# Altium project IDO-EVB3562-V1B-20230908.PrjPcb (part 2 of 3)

## Sheet P15.SchDoc
size 420 x 297 mm
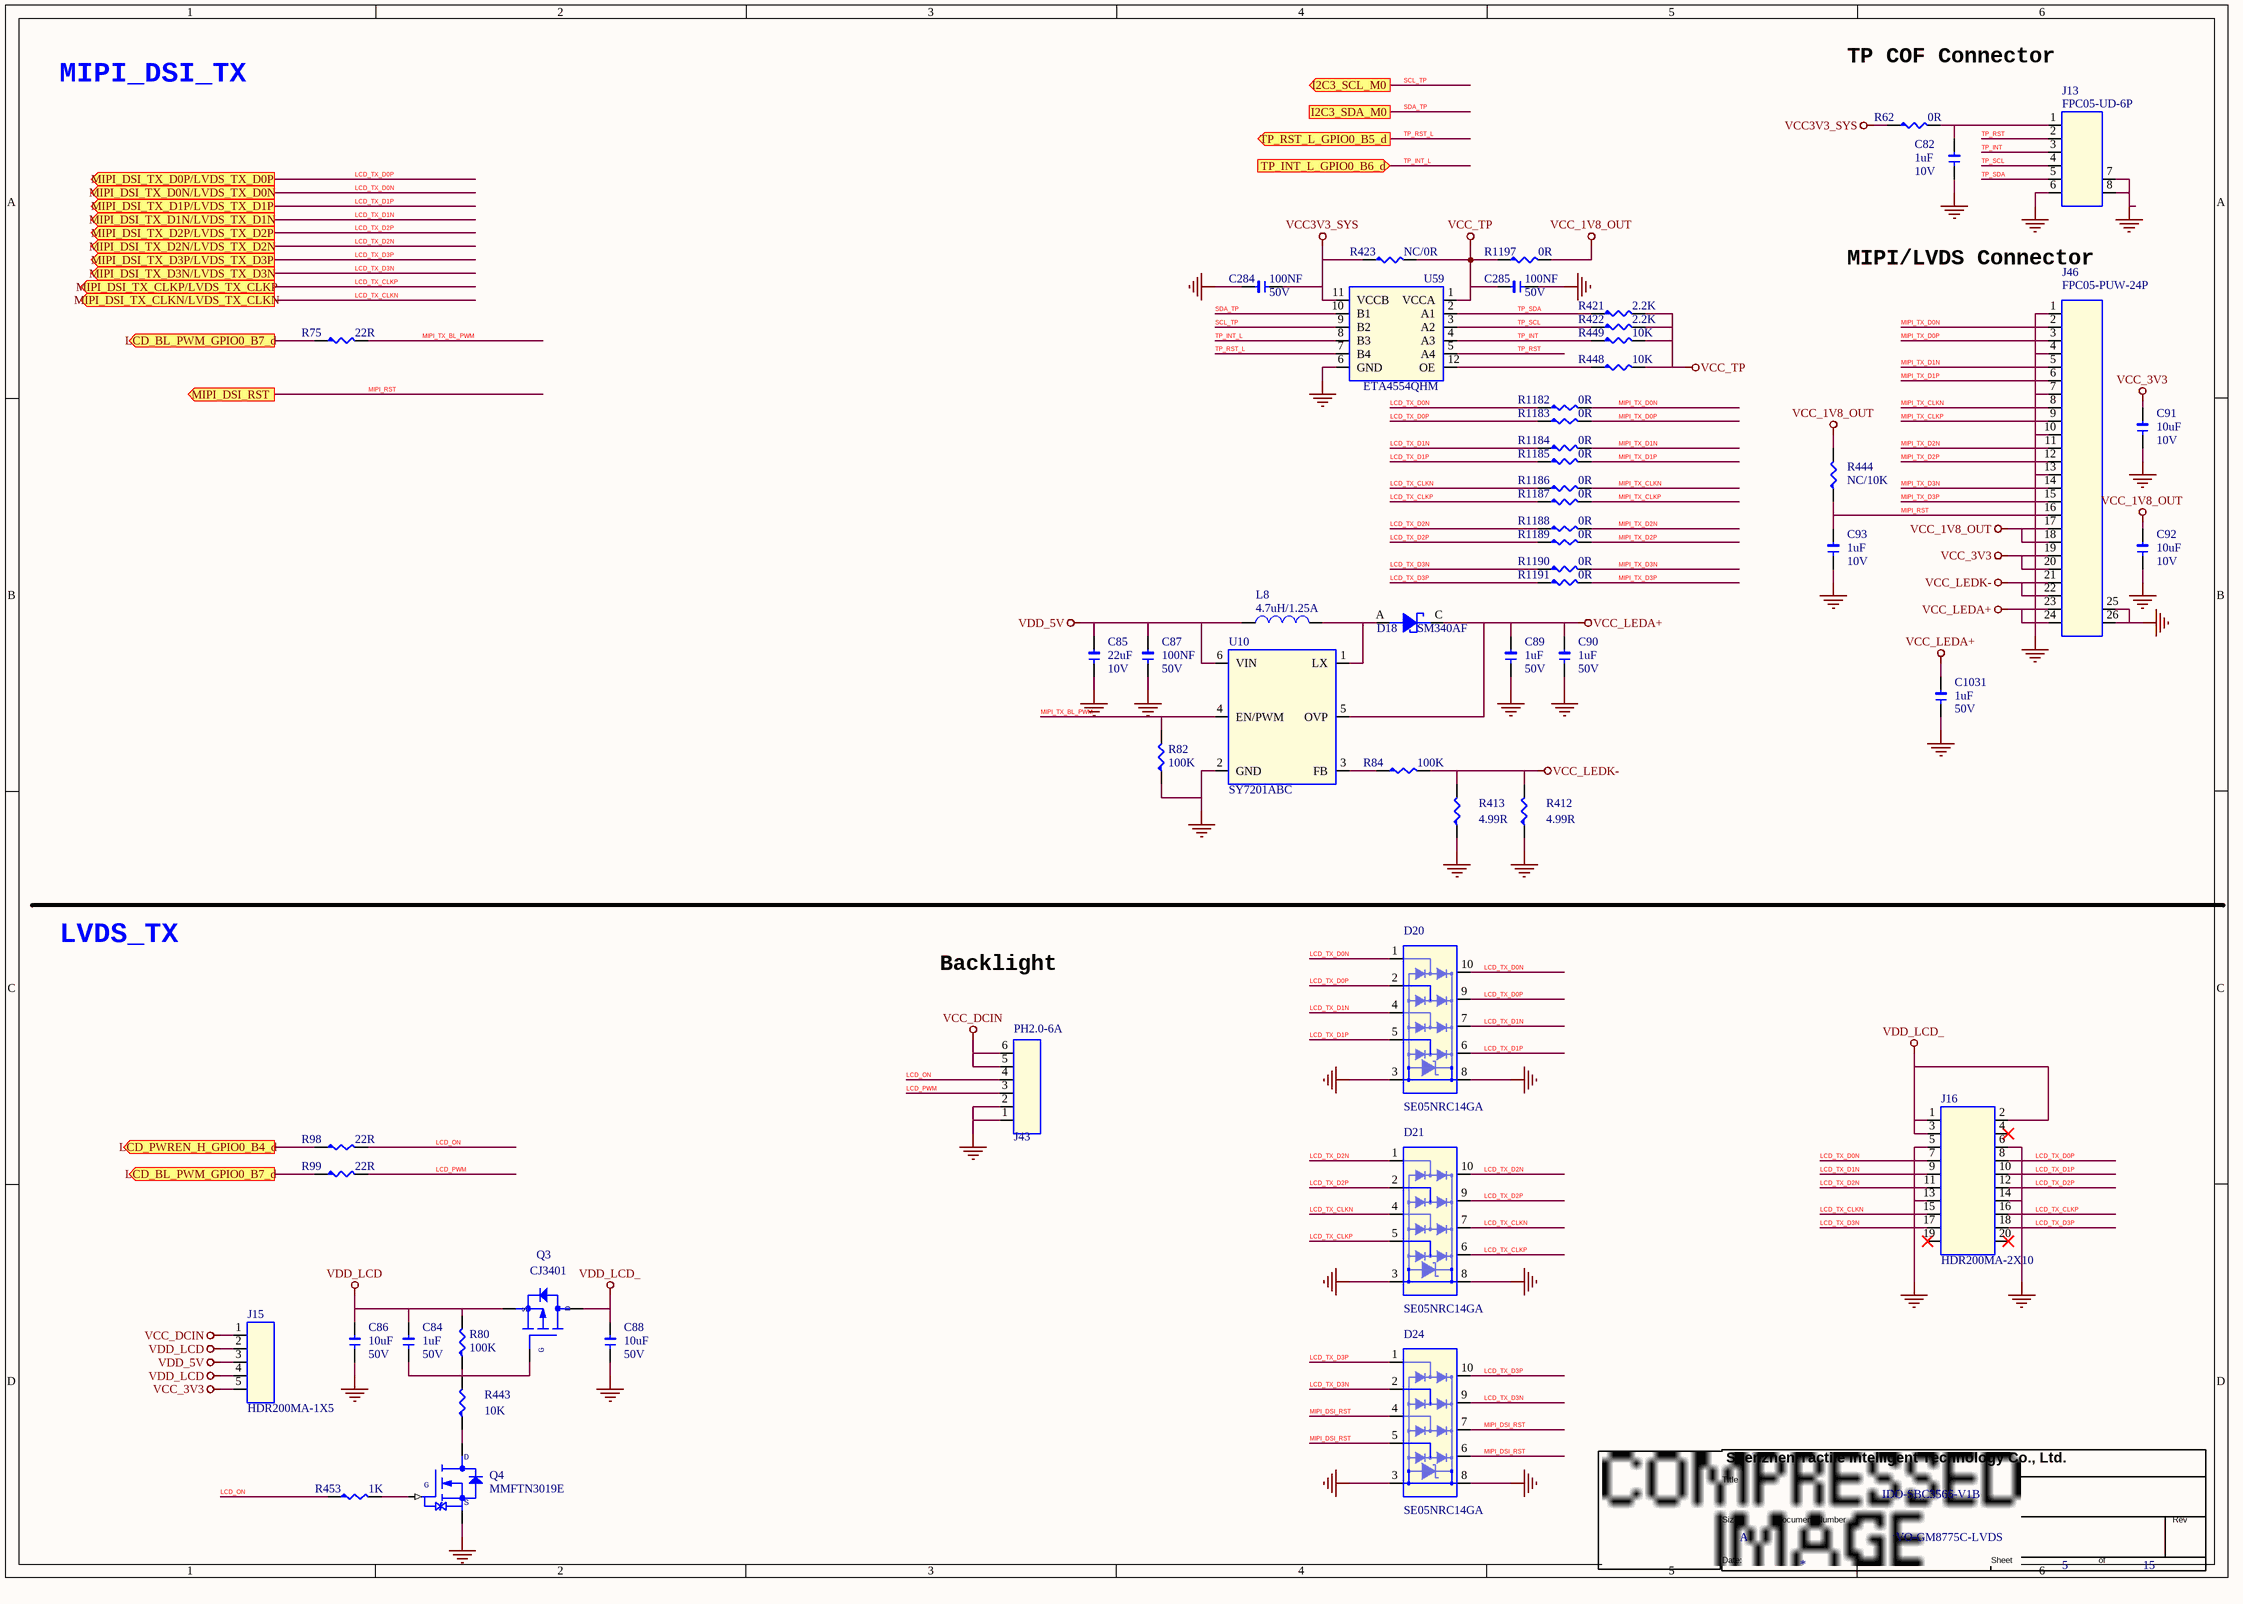
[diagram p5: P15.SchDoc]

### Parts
(Parts that share a designator on the sheet are numbered #1, #2 ... from top to bottom, then left to right.)
*#3  Page Count: 15  Page Number: 5  Page Size: A  Title: IDO-SBC3566-V1B  Doc: VO-GM8775C-LVDS  (hidden comment: TitleBlock1)  (graphical)
C82  1uF  DSC2: 10V  [1206]
C84  1uF  DSC2: 50V  [1206]
C85  22uF  DSC2: 10V  [1206]
C86  10uF  DSC2: 50V  [1206]
C87  100NF  DSC2: 50V  [1206]
C88  10uF  DSC2: 50V  [1206]
C89  1uF  DSC2: 50V  [1206]
C90  1uF  DSC2: 50V  [1206]
C91  10uF  DSC2: 10V  [1206]
C92  10uF  DSC2: 10V  [1206]
C93  1uF  DSC2: 10V  [1206]
C284  100NF  DSC2: 50V  [1206]
C285  100NF  DSC2: 50V  [1206]
C1031  1uF  DSC2: 50V  [1206]
D18  SM340AF  [SMAF]
D20  SE05NRC14GA  [DFN2510-10L]
D21  SE05NRC14GA  [DFN2510-10L]
D24  SE05NRC14GA  [DFN2510-10L]
J13  FPC05-UD-6P  [FPC05-6P]
J15  HDR200MA-1X5  [HDR200MA-1X5]
J16  HDR200MA-2X10  [HDR200MA-2X10]
J43  PH2.0-6A  [PH200-6A]
J46  FPC05-PUW-24P  [FPC05-24P]
L8  4.7uH/1.25A  [IND_252012]
Q3  CJ3401  [SOT23]
Q4  MMFTN3019E  [SOT523]
R62  0R  [R0402]
R75  22R  [R0402]
R80  100K  [R0402]
R82  100K  [R0402]
R84  100K  [R0402]
R98  22R  [R0402]
R99  22R  [R0402]
R412  4.99R  [R0603]
R413  4.99R  [R0603]
R421  2.2K  [R0402]
R422  2.2K  [R0402]
R423  NC/0R  [R0402]
R443  10K  [R0402]
R444  NC/10K  [R0402]
R448  10K  [R0402]
R449  10K  [R0402]
R453  1K  [R0402]
R1182  0R  [R0402]
R1183  0R  [R0402]
R1184  0R  [R0402]
R1185  0R  [R0402]
R1186  0R  [R0402]
R1187  0R  [R0402]
R1188  0R  [R0402]
R1189  0R  [R0402]
R1190  0R  [R0402]
R1191  0R  [R0402]
R1197  0R  [R0402]
U10  SY7201ABC  [SOT23-6]
U59  ETA4554QHM  [ETA4554-QFN12]

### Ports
I2C3_SCL_M0 (out), I2C3_SDA_M0, LCD_BL_PWM_GPIO0_B7_d (out), LCD_PWREN_H_GPIO0_B4_d (out), MIPI_DSI_RST (out), MIPI_DSI_TX_CLKN/LVDS_TX_CLKN (out), MIPI_DSI_TX_CLKP/LVDS_TX_CLKP (out), MIPI_DSI_TX_D0N/LVDS_TX_D0N (out), MIPI_DSI_TX_D0P/LVDS_TX_D0P (out), MIPI_DSI_TX_D1N/LVDS_TX_D1N (out), MIPI_DSI_TX_D1P/LVDS_TX_D1P (out), MIPI_DSI_TX_D2N/LVDS_TX_D2N (out), MIPI_DSI_TX_D2P/LVDS_TX_D2P (out), MIPI_DSI_TX_D3N/LVDS_TX_D3N (out), MIPI_DSI_TX_D3P/LVDS_TX_D3P (out), TP_INT_L_GPIO0_B6_d (in), TP_RST_L_GPIO0_B5_d (out)

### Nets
GND: C82.1 C85.1 C86.1 C87.1 C88.1 C89.1 C90.1 C91.1 C92.1 C93.1 C284.2 C285.1 C1031.1 D20.3 D20.8 D21.3 D21.8 D24.3 D24.8 J13.6 J13.7 J13.8 J16.5 J16.6 J16.13 J16.14 J43.1 J43.2 J46.1 J46.4 J46.7 J46.10 J46.13 J46.25 J46.26 Q4.2(SOURCE) R82.1 R412.1 R413.1 U10.2(GND) U59.6(GND)
VCC3V3_SYS: C284.1 R62.1 R423.1 U59.11(VCCB)
VCC_1V8_OUT: C92.2 J46.17 J46.18 R444.2 R1197.2
VCC_3V3: C91.2 J15.5 J46.19 J46.20
VCC_DCIN: J15.1 J43.5 J43.6
VCC_LEDA+: C89.2 C90.2 C1031.2 D18.C J46.23 J46.24 U10.5(OVP)
VCC_LEDK-: J46.21 J46.22 R84.2 R412.2 R413.2
VCC_TP: C285.2 R421.2 R422.2 R423.2 R448.2 R449.2 R1197.1 U59.1(VCCA)
VDD_5V: C85.2 C87.2 J15.3 L8.1 U10.6(VIN)
VDD_LCD: C84.2 C86.2 J15.2 J15.4 Q3.2(SOURCE) R80.2
VDD_LCD_: C88.2 J16.1 J16.2 J16.3 Q3.3(DRAIN)
LCD_ON: J43.4 R98.2 R453.1
LCD_PWM: J43.3 R99.2
LCD_TX_CLKN: D21.4 D21.7 J16.15 R1186.1 ; port MIPI_DSI_TX_CLKN/LVDS_TX_CLKN
LCD_TX_CLKP: D21.5 D21.6 J16.16 R1187.1 ; port MIPI_DSI_TX_CLKP/LVDS_TX_CLKP
LCD_TX_D0N: D20.1 D20.10 J16.7 R1182.1 ; port MIPI_DSI_TX_D0N/LVDS_TX_D0N
LCD_TX_D0P: D20.2 D20.9 J16.8 R1183.1 ; port MIPI_DSI_TX_D0P/LVDS_TX_D0P
LCD_TX_D1N: D20.4 D20.7 J16.9 R1184.1 ; port MIPI_DSI_TX_D1N/LVDS_TX_D1N
LCD_TX_D1P: D20.5 D20.6 J16.10 R1185.1 ; port MIPI_DSI_TX_D1P/LVDS_TX_D1P
LCD_TX_D2N: D21.1 D21.10 J16.11 R1188.1 ; port MIPI_DSI_TX_D2N/LVDS_TX_D2N
LCD_TX_D2P: D21.2 D21.9 J16.12 R1189.1 ; port MIPI_DSI_TX_D2P/LVDS_TX_D2P
LCD_TX_D3N: D24.2 D24.9 J16.17 R1190.1 ; port MIPI_DSI_TX_D3N/LVDS_TX_D3N
LCD_TX_D3P: D24.1 D24.10 J16.18 R1191.1 ; port MIPI_DSI_TX_D3P/LVDS_TX_D3P
MIPI_DSI_RST: D24.4 D24.5 D24.6 D24.7
MIPI_RST: C93.2 J46.16 R444.1 ; port MIPI_DSI_RST
MIPI_TX_BL_PWM: R75.2 R82.2 U10.4(EN/PWM)
MIPI_TX_CLKN: J46.8 R1186.2
MIPI_TX_CLKP: J46.9 R1187.2
MIPI_TX_D0N: J46.2 R1182.2
MIPI_TX_D0P: J46.3 R1183.2
MIPI_TX_D1N: J46.5 R1184.2
MIPI_TX_D1P: J46.6 R1185.2
MIPI_TX_D2N: J46.11 R1188.2
MIPI_TX_D2P: J46.12 R1189.2
MIPI_TX_D3N: J46.14 R1190.2
MIPI_TX_D3P: J46.15 R1191.2
SCL_TP: U59.9(B2) ; port I2C3_SCL_M0
SDA_TP: U59.10(B1) ; port I2C3_SDA_M0
TP_INT: J13.3 R449.1 U59.4(A3)
TP_INT_L: U59.8(B3) ; port TP_INT_L_GPIO0_B6_d
TP_RST: J13.2 U59.5(A4)
TP_RST_L: U59.7(B4) ; port TP_RST_L_GPIO0_B5_d
TP_SCL: J13.4 R422.1 U59.3(A2)
TP_SDA: J13.5 R421.1 U59.2(A1)
NetC82_2: C82.2 J13.1 R62.2
NetC84_1: C84.1 Q3.1(GATE) R80.1 R443.2
NetD18_A: D18.A L8.2 U10.1(LX)
NetM1_154: R98.1 ; port LCD_PWREN_H_GPIO0_B4_d
NetM1_157: R75.1 R99.1 ; port LCD_BL_PWM_GPIO0_B7_d
NetQ4_1: Q4.1(GATE) R453.2
NetQ4_3: Q4.3(DRAIN) R443.1
NetR84_1: R84.1 U10.3(FB)
NetR448_1: R448.1 U59.12(OE)

Not connected (* = marked no-connect by the designer): J16 4* 19* 20*

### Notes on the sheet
- MIPI_DSI_TX
- TP COF Connector
- MIPI/LVDS Connector
- LVDS_TX
- Backlight

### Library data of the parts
C82 = C-0402_Dup1: Part Number: C020102120064; Part Name: 贴片电容; Manufacture: 三星¦国巨¦村田; PCB Footprint: C0402; ERP Number: 1010200054; DSC1: ±10%; DSC3: X5R; ID: 64
C84 C89 C90 C1031 = C-0603: Manufacture: 三星¦国巨¦村田; Part Name: 贴片电容; Part Number: C020102120069; PCB Footprint: C0603; ID: 69; DSC3: X5R; DSC1: ±10%; ERP Number: 1010200142
C85 = C-0603: Manufacture: 三星¦国巨¦村田; Part Name: 贴片电容; Part Number: C020107143899; PCB Footprint: C0603; ID: 83; DSC3: X5R; DSC1: ±20%
C86 = C-1206_Dup1: Part Number: C020103263826; Part Name: 贴片电容; Manufacture: 三星¦国巨¦村田; DSC1: ±10%; DSC3: X5R; ID: 79; PCB Footprint: C1206
C87 = C-0402_Dup1: Manufacture: 三星¦国巨¦村田; Part Name: 贴片电容; Part Number: C020102120061; PCB Footprint: C0402; ID: 61; DSC3: X7R; DSC1: ±10%; ERP Number: 1010200128
C88 = C-1206_Dup1: Manufacture: 三星¦国巨¦村田; Part Name: 贴片电容; Part Number: C020103263826; ID: 79; DSC3: X5R; DSC1: ±10%; PCB Footprint: C1206
C91 C92 = C-0603: Part Number: C020102120071; Part Name: 贴片电容; Manufacture: 三星¦国巨¦村田; PCB Footprint: C0603; ERP Number: 1010200076; DSC1: ±20%; DSC3: X5R; ID: 71
C93 = C-0402_Dup1: Manufacture: 三星¦国巨¦村田; Part Name: 贴片电容; Part Number: C020102120064; PCB Footprint: C0402; ID: 64; DSC3: X5R; DSC1: ±10%; ERP Number: 1010200054
C284 C285 = C-0402_Dup1: Manufacture: 三星¦国巨¦村田; Part Name: 贴片电容; Part Number: C020102120061; ID: 61; DSC3: X7R; DSC1: ±10%; ERP Number: 1010200128; PCB Footprint: C0402
D18 = DI-XI-S: Manufacture: 乐山无线电; Part Name: 肖特基二级管; Part Number: C040202220007; CLASS: IC; Solder: 推荐; ID: 7; DSC3: VF=500mV/3A; DSC2: IF=3A; DSC1: VR=40V
D20 D21 = DI-ESD-SE05NRC14GA: Manufacture: 硕凯; Part Number: C040504013981; Part Name: ESD; Solder: 推荐; ID: 8; DSC5: Cj=0.4pF; DSC4: Vc=20V; DSC3: Vbr=8V; DSC2: Vdc=5V; DSC1: 双向
D24 = DI-ESD-SE05NRC14GA: Part Name: ESD; Part Number: C040504013981; Manufacture: 硕凯; DSC1: 双向; DSC2: Vdc=5V; DSC3: Vbr=8V; DSC4: Vc=20V; DSC5: Cj=0.4pF; ID: 8; Solder: 推荐
J13 = J-FPC-6P: Part Name: FPC座; DSC1: 6P; DSC2: 0.5mm间距; DSC3: 双面触点 前插后压 卧贴; DSC4: H=2mm; DSC5: 镀锡; DSC6: X05A20H06T（星坤）; ID: 41
J15 = J-HDR-5: Part Number: J010203194650; Part Name: 单排针; DSC1: 单排单塑; DSC2: 1x5; DSC3: 2mm脚距; DSC4: 通孔直针; DSC5: 针长8.8mm  2.8+2(H塑高)+4 mm; DSC6: 黑胶; DSC7: X4611WV-05I-C28D40（星坤）; ID: 82
J16 = J-HDR-D-20: Part Number: J010102760009; Part Name: 双排针; DSC1: 双排单塑; DSC2: 2x10; DSC3: 2mm脚距; DSC4: 通孔直针; DSC5: 针长8.8mm  2.8+2(H塑高)+4 mm; DSC6: 黑胶; DSC7: X4621WV-2x10I-C28D40（星坤）; ID: 9
J43 = J-H-6P: Part Name: PH; DSC1: 6p; DSC2: 2.0mm间距; DSC3: 通孔180度直针; DSC4: 红色胶壳 耐高温; DSC5: A2001WV-6P-1-RD(CJT); ID: 80
J46 = J-FPC-24P: Part Name: FPC座; Part Number: J030102870021; ID: 34; DSC6: X05B20U24T(星坤); DSC5: 镀锡; DSC4: H=2mm; DSC3: 上接 抽拉式 卧贴; DSC2: 0.5mm间距; DSC1: 24P
L8 = L-IND_Dup1: Manufacture: 宗成¦长江微电¦顺络; Part Name: 功率电感; ID: 54; DSC8: ZCRH252012-4.7uH-M(宗成); DSC7: FHD252012S-4R7MT(长江微电); DSC6: WPN252012H4R7MT(顺络); DSC5: 2.5*2.0*1.2mm; DSC4: 260mΩ; DSC3: Irms=1.25A; DSC2: Isat=1.6A; DSC1: ±20%
Q3 = P-MOS: Part Number: C030202190001; Manufacture: 长电; ERP Number: 1010800001; DSC1: Vds=-30V; DSC2: Id=-4.2A; DSC3: Vgs(th)=-1.3V; DSC4: Vgs=±12V; DSC5: pd=350mW; ID: 1
Q4 = N-MOS-Q: Part Number: C030202190004; Part Name: N-MOS; Manufacture: 先科; ERP Number: 1010800011; DSC1: Vds=30V; DSC2: Id=100mA; DSC3: Vgs(th)=1.5V; DSC4: Vgs=±20V; DSC5: pd=150mW; ID: 4
R62 R1197 = R-0402_Dup3: Part Name: 贴片电阻; Part Number: C011002080413; DSC1: ±1%; DSC2: 1/16W; ID: 413
R75 R98 R99 = R-0402_Dup3: Part Name: 贴片电阻; Part Number: C011002080262; ERP Number: 1010200173; DSC1: ±5%; DSC2: 1/16W; ID: 262
R80 R82 R84 = R-0402_Dup3: Part Number: C011002080353; Part Name: 贴片电阻; ID: 353; DSC2: 1/16W; DSC1: ±5%; ERP Number: 1010200103
R412 = R-0603_Dup1: Part Number: C011002081238; Part Name: 贴片电阻; ID: 1,238; DSC2: 1/10W; DSC1: ±1%
R413 = R-0603_Dup1: Part Name: 贴片电阻; Part Number: C011002081238; DSC1: ±1%; DSC2: 1/10W; ID: 1,238
R421 R422 = R-0402_Dup3: Part Number: C011002080778; Part Name: 贴片电阻; ID: 778; DSC2: 1/16W; DSC1: ±1%
R423 = R-0402_Dup3: Part Number: C011002080413; Part Name: 贴片电阻; ID: 413; DSC2: 1/16W; DSC1: ±1%
R443 R444 = R-0402_Dup3: Part Number: C011002080856; Part Name: 贴片电阻; ID: 856; DSC2: 1/16W; DSC1: ±1%; ERP Number: 1010200140
R448 R449 = R-0402_Dup3: Part Name: 贴片电阻; Part Number: C011002080856; ERP Number: 1010200140; DSC1: ±1%; DSC2: 1/16W; ID: 856
R453 = R-0402_Dup3: Part Name: 贴片电阻; Part Number: C011002080742; ERP Number: 1010200113; DSC1: ±1%; DSC2: 1/16W; ID: 742
R1182-R1191 = R-0402_Dup3: Part Name: 贴片电阻; Part Number: C011002080217; ERP Number: 1010200100; DSC1: ±5%; DSC2: 1/16W; ID: 217
U10 = U-SY7201ABC: Manufacture: 矽力杰; Part Number: C070202410024; Part Name: DCDC; ID: 24; Solder: 量产; DSC7: Boost LED驱动; DSC6: 1MHz; DSC5: 0.9; DSC4: Vfb=200mV; DSC3: Io=2A; DSC2: Vo=30V; DSC1: Vi=2.5-30V; ERP Number: 1010100053
U59 = U-ETA4554QHM: Part Name: 逻辑缓冲器; Part Number: C080105124705; Manufacture: ETA 钰泰; DSC1: 4位 高速缓冲 24Mbps VCC=1.65V-5.5V; DSC2: QFN12; DSC3: -40℃~+85℃; ID: 11

## Sheet P16.SchDoc
size 420 x 297 mm
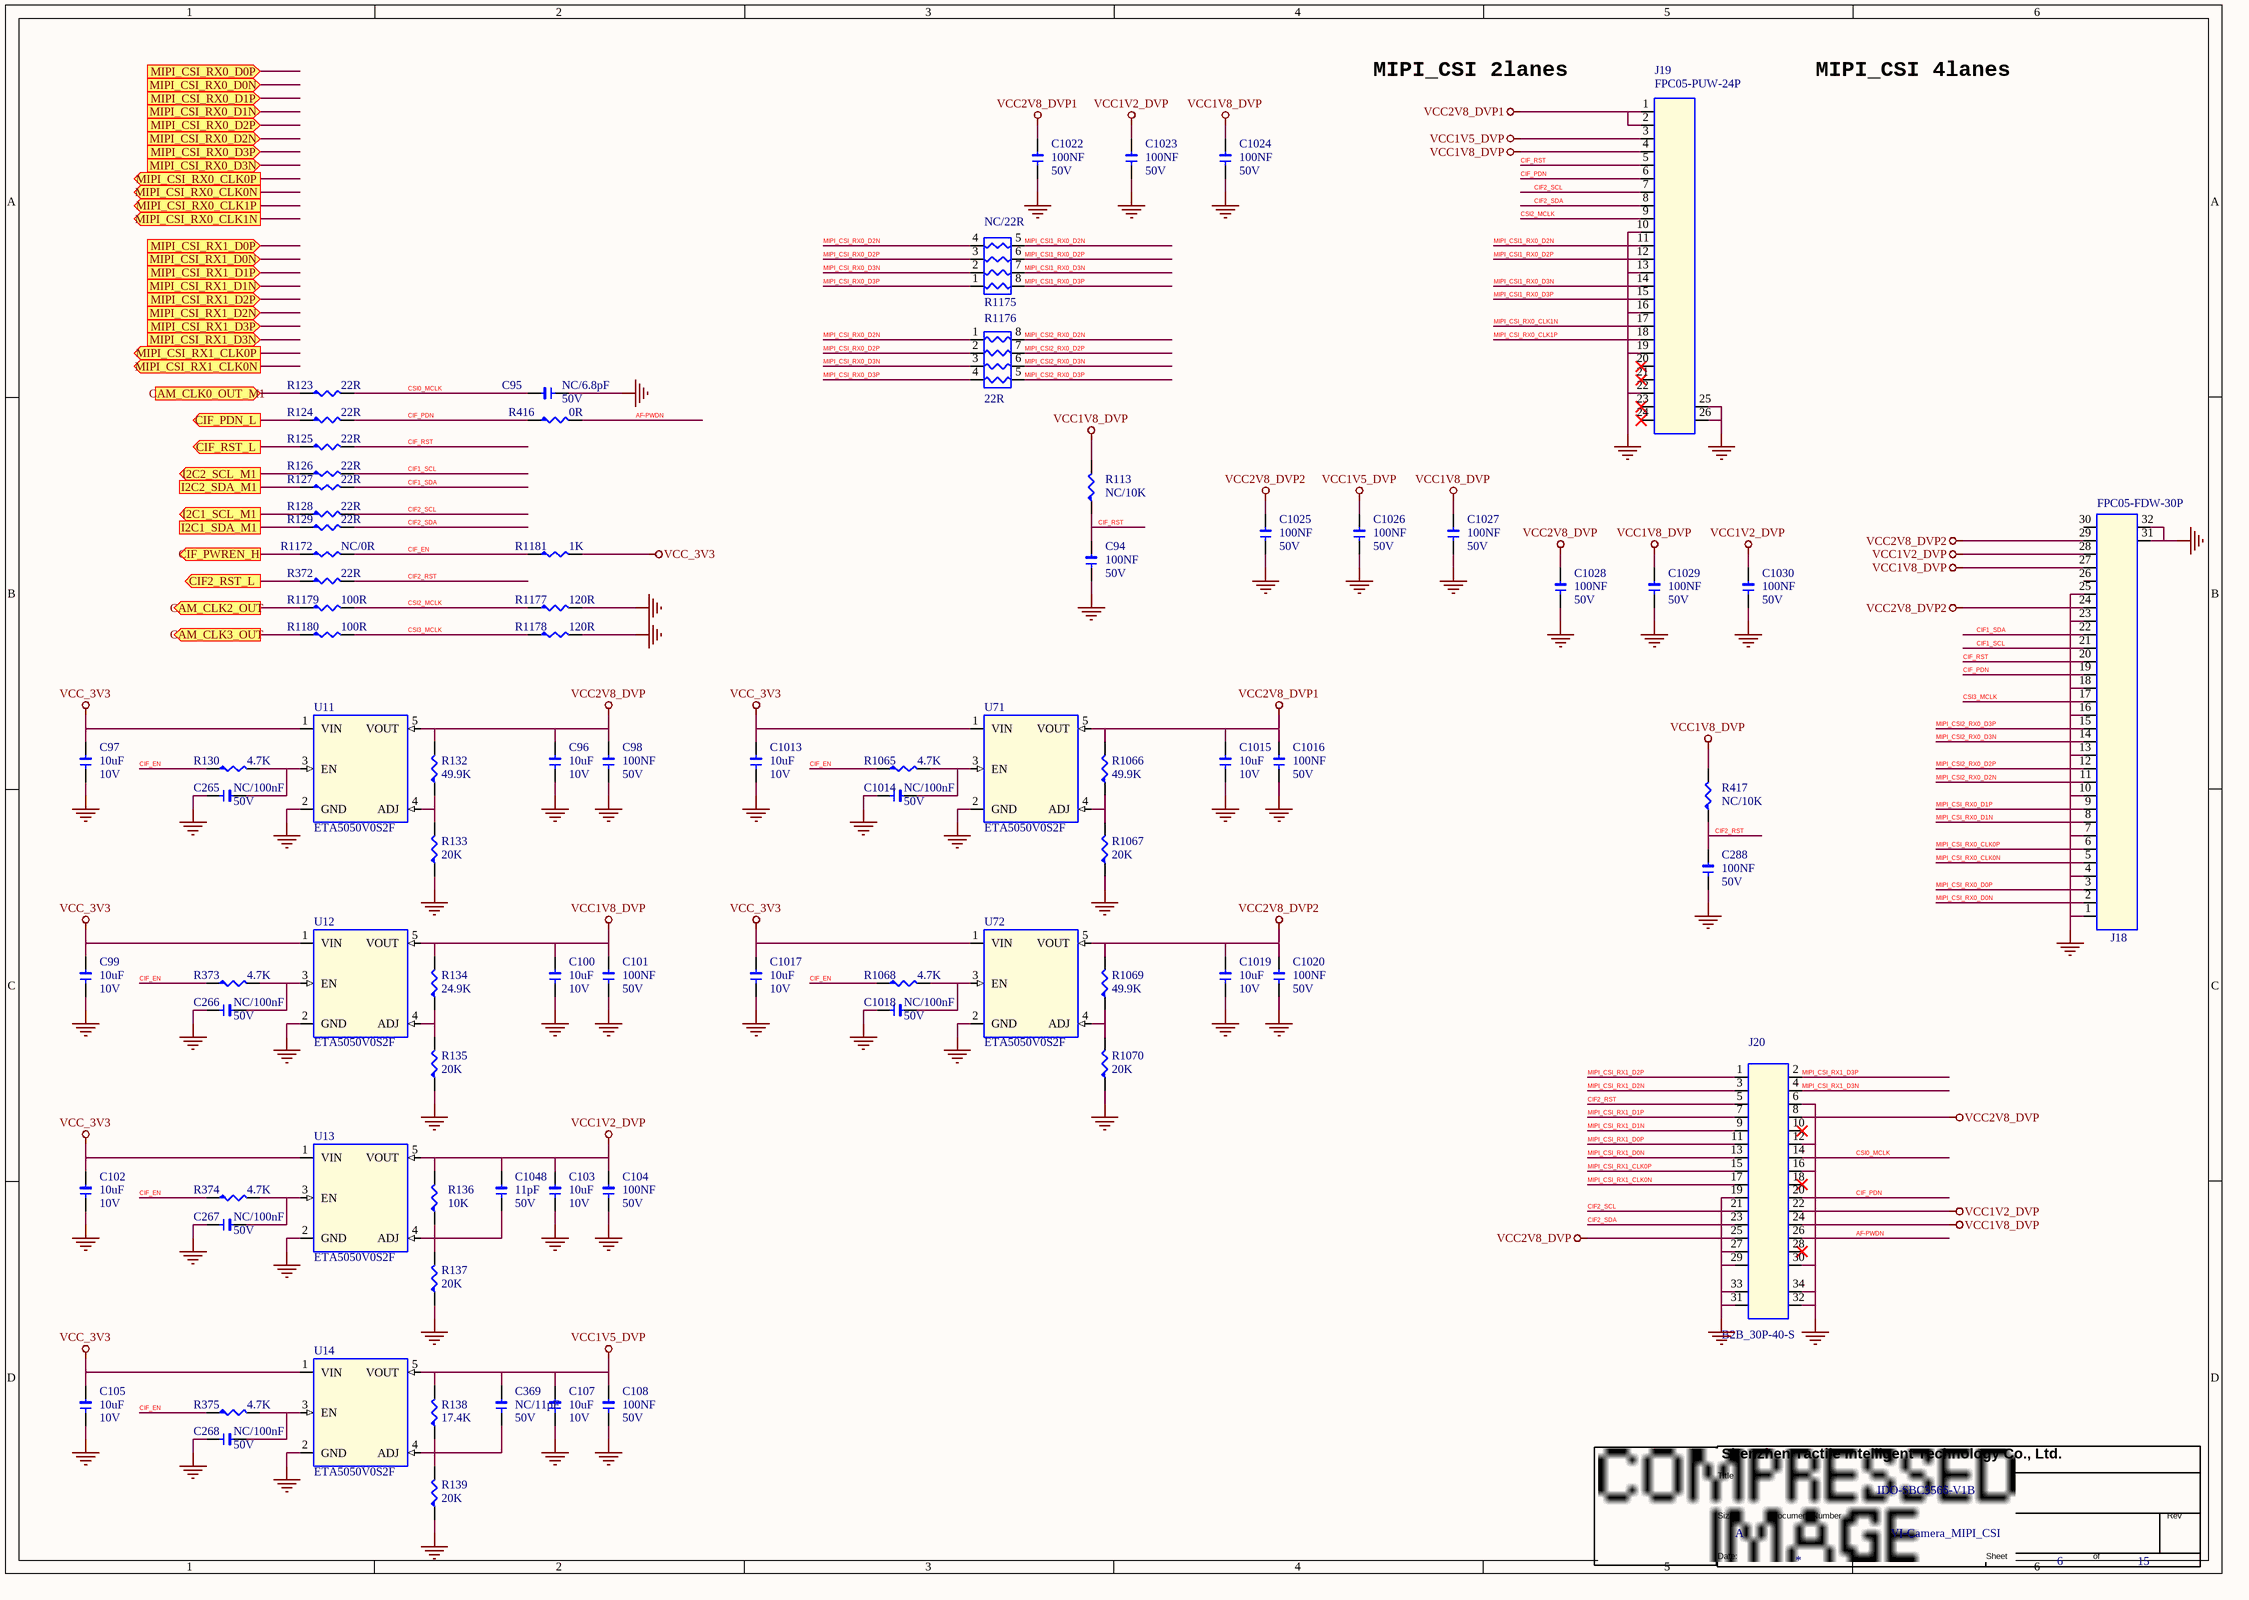
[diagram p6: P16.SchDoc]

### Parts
(Parts that share a designator on the sheet are numbered #1, #2 ... from top to bottom, then left to right.)
*#4  Page Count: 15  Page Number: 6  Page Size: A  Title: IDO-SBC3566-V1B  Doc: VI-Camera_MIPI_CSI  (hidden comment: TitleBlock1)  (graphical)
C94  100NF  DSC2: 50V  [1206]
C95  NC/6.8pF  DSC2: 50V  [1206]
C96  10uF  DSC2: 10V  [1206]
C97  10uF  DSC2: 10V  [1206]
C98  100NF  DSC2: 50V  [1206]
C99  10uF  DSC2: 10V  [1206]
C100  10uF  DSC2: 10V  [1206]
C101  100NF  DSC2: 50V  [1206]
C102  10uF  DSC2: 10V  [1206]
C103  10uF  DSC2: 10V  [1206]
C104  100NF  DSC2: 50V  [1206]
C105  10uF  DSC2: 10V  [1206]
C107  10uF  DSC2: 10V  [1206]
C108  100NF  DSC2: 50V  [1206]
C265  NC/100nF  DSC2: 50V  [1206]
C266  NC/100nF  DSC2: 50V  [1206]
C267  NC/100nF  DSC2: 50V  [1206]
C268  NC/100nF  DSC2: 50V  [1206]
C288  100NF  DSC2: 50V  [1206]
C369  NC/11pF  DSC2: 50V  [1206]
C1013  10uF  DSC2: 10V  [1206]
C1014  NC/100nF  DSC2: 50V  [1206]
C1015  10uF  DSC2: 10V  [1206]
C1016  100NF  DSC2: 50V  [1206]
C1017  10uF  DSC2: 10V  [1206]
C1018  NC/100nF  DSC2: 50V  [1206]
C1019  10uF  DSC2: 10V  [1206]
C1020  100NF  DSC2: 50V  [1206]
C1022  100NF  DSC2: 50V  [1206]
C1023  100NF  DSC2: 50V  [1206]
C1024  100NF  DSC2: 50V  [1206]
C1025  100NF  DSC2: 50V  [1206]
C1026  100NF  DSC2: 50V  [1206]
C1027  100NF  DSC2: 50V  [1206]
C1028  100NF  DSC2: 50V  [1206]
C1029  100NF  DSC2: 50V  [1206]
C1030  100NF  DSC2: 50V  [1206]
C1048  11pF  DSC2: 50V  [1206]
J18  FPC05-FDW-30P  [FPC05-30P]
J19  FPC05-PUW-24P  [FPC05-24P]
J20  B2B_30P-40-S  [B2B_30P-40-S]
R113  NC/10K  [R0402]
R123  22R  [R0402]
R124  22R  [R0402]
R125  22R  [R0402]
R126  22R  [R0402]
R127  22R  [R0402]
R128  22R  [R0402]
R129  22R  [R0402]
R130  4.7K  [R0402]
R132  49.9K  [R0402]
R133  20K  [R0402]
R134  24.9K  [R0402]
R135  20K  [R0402]
R136  10K  [R0402]
R137  20K  [R0402]
R138  17.4K  [R0402]
R139  20K  [R0402]
R372  22R  [R0402]
R373  4.7K  [R0402]
R374  4.7K  [R0402]
R375  4.7K  [R0402]
R416  0R  [R0402]
R417  NC/10K  [R0402]
R1065  4.7K  [R0402]
R1066  49.9K  [R0402]
R1067  20K  [R0402]
R1068  4.7K  [R0402]
R1069  49.9K  [R0402]
R1070  20K  [R0402]
R1172  NC/0R  [R0402]
R1175  NC/22R  [RN_0402X4]
R1176  22R  [RN_0402X4]
R1177  120R  [R0402]
R1178  120R  [R0402]
R1179  100R  [R0402]
R1180  100R  [R0402]
R1181  1K  [R0402]
U11  ETA5050V0S2F  [SOT23-5]
U12  ETA5050V0S2F  [SOT23-5]
U13  ETA5050V0S2F  [SOT23-5]
U14  ETA5050V0S2F  [SOT23-5]
U71  ETA5050V0S2F  [SOT23-5]
U72  ETA5050V0S2F  [SOT23-5]

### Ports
CAM_CLK0_OUT_M1 (in), CAM_CLK2_OUT (out), CAM_CLK3_OUT (out), CIF2_RST_L (out), CIF_PDN_L (out), CIF_PWREN_H (out), CIF_RST_L (out), I2C1_SCL_M1 (out), I2C1_SDA_M1, I2C2_SCL_M1 (out), I2C2_SDA_M1, MIPI_CSI_RX0_CLK0N (out), MIPI_CSI_RX0_CLK0P (out), MIPI_CSI_RX0_CLK1N (out), MIPI_CSI_RX0_CLK1P (out), MIPI_CSI_RX0_D0N (in), MIPI_CSI_RX0_D0P (in), MIPI_CSI_RX0_D1N (in), MIPI_CSI_RX0_D1P (in), MIPI_CSI_RX0_D2N (in), MIPI_CSI_RX0_D2P (in), MIPI_CSI_RX0_D3N (in), MIPI_CSI_RX0_D3P (in), MIPI_CSI_RX1_CLK0N (out), MIPI_CSI_RX1_CLK0P (out), MIPI_CSI_RX1_D0N (in), MIPI_CSI_RX1_D0P (in), MIPI_CSI_RX1_D1N (in), MIPI_CSI_RX1_D1P (in), MIPI_CSI_RX1_D2N (in), MIPI_CSI_RX1_D2P (in), MIPI_CSI_RX1_D3N (in), MIPI_CSI_RX1_D3P (in)

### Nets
GND: C94.1 C95.1 C96.1 C97.1 C98.1 C99.1 C100.1 C101.1 C102.1 C103.1 C104.1 C105.1 C107.1 C108.1 C265.1 C266.1 C267.1 C268.1 C288.1 C1013.1 C1014.1 C1015.1 C1016.1 C1017.1 C1018.1 C1019.1 C1020.1 C1022.1 C1023.1 C1024.1 C1025.1 C1026.1 C1027.1 C1028.1 C1029.1 C1030.1 J18.1 J18.4 J18.7 J18.10 J18.13 J18.16 J18.18 J18.23 J18.25 J18.31 J18.32 J19.10 J19.13 J19.16 J19.19 J19.22 J19.25 J19.26 J20.6 J20.12 J20.16 J20.19 J20.27 J20.29 J20.30 J20.31 J20.32 J20.33 J20.34 R133.1 R135.1 R137.1 R139.1 R1067.1 R1070.1 R1177.2 R1178.2 U11.2(GND) U12.2(GND) U13.2(GND) U14.2(GND) U71.2(GND) U72.2(GND)
VCC1V2_DVP: C103.2 C104.2 C1023.2 C1030.2 C1048.2 J18.28 J20.22 R136.2 U13.5(VOUT)
VCC1V5_DVP: C107.2 C108.2 C369.2 C1026.2 J19.3 R138.2 U14.5(VOUT)
VCC1V8_DVP: C100.2 C101.2 C1024.2 C1027.2 C1029.2 J18.27 J19.4 J20.24 R113.2 R134.2 R417.2 U12.5(VOUT)
VCC2V8_DVP: C96.2 C98.2 C1028.2 J20.8 J20.25 R132.2 U11.5(VOUT)
VCC2V8_DVP1: C1015.2 C1016.2 C1022.2 J19.1 J19.2 R1066.2 U71.5(VOUT)
VCC2V8_DVP2: C1019.2 C1020.2 C1025.2 J18.24 J18.29 R1069.2 U72.5(VOUT)
VCC_3V3: C97.2 C99.2 C102.2 C105.2 C1013.2 C1017.2 R1181.2 U11.1(VIN) U12.1(VIN) U13.1(VIN) U14.1(VIN) U71.1(VIN) U72.1(VIN)
AF-PWDN: J20.26 R416.2
CIF1_SCL: J18.21 R126.2
CIF1_SDA: J18.22 R127.2
CIF2_RST: C288.2 J20.5 R372.2 R417.1
CIF2_SCL: J19.7 J20.21 R128.2
CIF2_SDA: J19.8 J20.23 R129.2
CIF_EN: R130.1 R373.1 R374.1 R375.1 R1065.1 R1068.1 R1172.2 R1181.1
CIF_PDN: J18.19 J19.6 J20.20 R124.2 R416.1
CIF_RST: C94.2 J18.20 J19.5 R113.1 R125.2
CSI0_MCLK: C95.2 J20.14 R123.2
CSI2_MCLK: J19.9 R1177.1 R1179.2
CSI3_MCLK: J18.17 R1178.1 R1180.2
MIPI_CSI1_RX0_D2N: J19.11 R1175.5
MIPI_CSI1_RX0_D2P: J19.12 R1175.6
MIPI_CSI1_RX0_D3N: J19.14 R1175.7
MIPI_CSI1_RX0_D3P: J19.15 R1175.8
MIPI_CSI2_RX0_D2N: J18.11 R1176.8
MIPI_CSI2_RX0_D2P: J18.12 R1176.7
MIPI_CSI2_RX0_D3N: J18.14 R1176.6
MIPI_CSI2_RX0_D3P: J18.15 R1176.5
MIPI_CSI_RX0_CLK0N: J18.5
MIPI_CSI_RX0_CLK0P: J18.6
MIPI_CSI_RX0_CLK1N: J19.17
MIPI_CSI_RX0_CLK1P: J19.18
MIPI_CSI_RX0_D0N: J18.2
MIPI_CSI_RX0_D0P: J18.3
MIPI_CSI_RX0_D1N: J18.8
MIPI_CSI_RX0_D1P: J18.9
MIPI_CSI_RX0_D2N: R1175.4 R1176.1
MIPI_CSI_RX0_D2P: R1175.3 R1176.2
MIPI_CSI_RX0_D3N: R1175.2 R1176.3
MIPI_CSI_RX0_D3P: R1175.1 R1176.4
MIPI_CSI_RX1_CLK0N: J20.17
MIPI_CSI_RX1_CLK0P: J20.15
MIPI_CSI_RX1_D0N: J20.13
MIPI_CSI_RX1_D0P: J20.11
MIPI_CSI_RX1_D1N: J20.9
MIPI_CSI_RX1_D1P: J20.7
MIPI_CSI_RX1_D2N: J20.3
MIPI_CSI_RX1_D2P: J20.1
MIPI_CSI_RX1_D3N: J20.4
MIPI_CSI_RX1_D3P: J20.2
NetC265_2: C265.2 R130.2 U11.3(EN)
NetC266_2: C266.2 R373.2 U12.3(EN)
NetC267_2: C267.2 R374.2 U13.3(EN)
NetC268_2: C268.2 R375.2 U14.3(EN)
NetC369_1: C369.1 R138.1 R139.2 U14.4(ADJ)
NetC1014_2: C1014.2 R1065.2 U71.3(EN)
NetC1018_2: C1018.2 R1068.2 U72.3(EN)
NetC1048_1: C1048.1 R136.1 R137.2 U13.4(ADJ)
NetM1_83: R1180.1 ; port CAM_CLK3_OUT
NetM1_84: R1179.1 ; port CAM_CLK2_OUT
NetM1_87: R1172.1 ; port CIF_PWREN_H
NetM1_88: R372.1 ; port CIF2_RST_L
NetM1_89: R124.1 ; port CIF_PDN_L
NetM1_90: R125.1 ; port CIF_RST_L
NetM1_93: R126.1 ; port I2C2_SCL_M1
NetM1_94: R127.1 ; port I2C2_SDA_M1
NetM1_109: R123.1 ; port CAM_CLK0_OUT_M1
NetM1_112: R128.1 ; port I2C1_SCL_M1
NetM1_113: R129.1 ; port I2C1_SDA_M1
NetR132_1: R132.1 R133.2 U11.4(ADJ)
NetR134_1: R134.1 R135.2 U12.4(ADJ)
NetR1066_1: R1066.1 R1067.2 U71.4(ADJ)
NetR1069_1: R1069.1 R1070.2 U72.4(ADJ)

Not connected (* = marked no-connect by the designer): J18 26 30; J19 20* 21* 23* 24*; J20 10* 18* 28*

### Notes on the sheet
- MIPI_CSI 2lanes
- MIPI_CSI 4lanes

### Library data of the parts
C94 = C-0402_Dup1: Part Number: C020102120061; Part Name: 贴片电容; Manufacture: 三星¦国巨¦村田; PCB Footprint: C0402; ERP Number: 1010200128; DSC1: ±10%; DSC3: X7R; ID: 61
C95 = C-0402_Dup1: Part Number: C020102120018; Part Name: 贴片电容; Manufacture: 三星¦国巨¦村田; PCB Footprint: C0402; ERP Number: 1010200056; DSC1: ±0.25PF; DSC3: C0G; ID: 18
C96 C100 C103 C107 = C-0603: Manufacture: 三星¦国巨¦村田; Part Name: 贴片电容; Part Number: C020102120071; PCB Footprint: C0603; ID: 71; DSC3: X5R; DSC1: ±20%; ERP Number: 1010200076
C97 C99 C102 C105 = C-0603: as C91 on sheet P15
C98 C101 C104 C108 C265-C268 C1022 C1024 C1026 C1028 C1030 = C-0402_Dup2: Manufacture: 三星¦国巨¦村田; Part Name: 贴片电容; Part Number: C020102120061; PCB Footprint: C0402; ID: 61; DSC3: X7R; DSC1: ±10%; ERP Number: 1010200128
C288 = C-0402_Dup1: as C87 on sheet P15
C369 = C-0402_Dup1: Part Number: C020102120022; Part Name: 贴片电容; Manufacture: 三星¦国巨¦村田; DSC1: ±5%; DSC3: C0G; ID: 22; PCB Footprint: C0402
C1013 C1017 = C-0603: Part Number: C020102120071; Part Name: 贴片电容; Manufacture: 三星¦国巨¦村田; ERP Number: 1010200076; DSC1: ±20%; DSC3: X5R; ID: 71; PCB Footprint: C0603
C1014 C1016 C1018 C1020 = C-0402_Dup2: Manufacture: 三星¦国巨¦村田; Part Name: 贴片电容; Part Number: C020102120061; ID: 61; DSC3: X7R; DSC1: ±10%; ERP Number: 1010200128; PCB Footprint: C0402
C1015 C1019 = C-0603: Manufacture: 三星¦国巨¦村田; Part Name: 贴片电容; Part Number: C020102120071; ID: 71; DSC3: X5R; DSC1: ±20%; ERP Number: 1010200076; PCB Footprint: C0603
C1023 C1025 C1027 C1029 = C-0402_Dup2: Part Number: C020102120061; Part Name: 贴片电容; Manufacture: 三星¦国巨¦村田; PCB Footprint: C0402; ERP Number: 1010200128; DSC1: ±10%; DSC3: X7R; ID: 61
C1048 = C-0402_Dup1: Manufacture: 三星¦国巨¦村田; Part Name: 贴片电容; Part Number: C020102120022; ID: 22; DSC3: C0G; DSC1: ±5%; PCB Footprint: C0402
J18 = J-FPC-30P: Part Name: FPC座; Part Number: J030102870078; ID: 19; DSC6: X05A20L30T(星坤); DSC5: 镀锡; DSC4: H=2mm; DSC3: 下接 翻盖 卧贴; DSC2: 0.5mm间距; DSC1: 30P
J19 = J-FPC-24P: as J46 on sheet P15
J20 = J-FPC-30P_1: Part Name: BTB座; ID: 19; DSC1: 30P
R113 R136 = R-0402_Dup3: as R448 on sheet P15
R123 = R-0402_Dup3: as R75 on sheet P15
R124-R129 R372 = R-0402_Dup3: Part Number: C011002080262; Part Name: 贴片电阻; ID: 262; DSC2: 1/16W; DSC1: ±5%; ERP Number: 1010200173
R130 R373-R375 R1065 R1068 = R-0402_Dup3: Part Number: C011002080818; Part Name: 贴片电阻; ID: 818; DSC2: 1/16W; DSC1: ±1%; ERP Number: 1010200445
R132 R1066 R1069 = R-0402_Dup3: Part Number: C011002080938; Part Name: 贴片电阻; ID: 938; DSC2: 1/16W; DSC1: ±1%
R133 R135 R137 R139 R1067 R1070 = R-0402_Dup3: Part Number: C011002080335; Part Name: 贴片电阻; ID: 335; DSC2: 1/16W; DSC1: ±5%
R134 = R-0402_Dup3: Part Number: C011002080900; Part Name: 贴片电阻; ID: 900; DSC2: 1/16W; DSC1: ±1%; ERP Number: 1010200327
R138 = R-0402_Dup3: Part Number: C011002080882; Part Name: 贴片电阻; ID: 882; DSC2: 1/16W; DSC1: ±1%
R416 = R-0402_Dup3: as R1182-R1191 on sheet P15
R417 = R-0402_Dup3: as R443 on sheet P15
R1172 = R-0402_Dup3: Part Number: C011002080217; Part Name: 贴片电阻; ID: 217; DSC2: 1/16W; DSC1: ±5%; ERP Number: 1010200100
R1175 R1176 = RN_0402X4: Part Number: C010302090004; Part Name: 贴片排阻; DSC2: 1/16W; DSC1: ±5%; ID: 4
R1177 R1178 = R-0402_Dup3: Part Name: 贴片电阻; Part Number: C011002080638; DSC1: ±1%; DSC2: 1/16W; ID: 638
R1179 R1180 = R-0402_Dup3: Part Number: C011002080630; Part Name: 贴片电阻; ID: 630; DSC2: 1/16W; DSC1: ±1%; ERP Number: 1010200450
R1181 = R-0402_Dup3: Part Number: C011002080742; Part Name: 贴片电阻; ID: 742; DSC2: 1/16W; DSC1: ±1%; ERP Number: 1010200113
U11 U71 U72 = U-ETA5050: Manufacture: ETA; Part Number: C070111104620; Part Name: LDO; Solder: 推荐; ID: 28; DSC5: Iq=40uA; DSC3: Io=500mA; DSC2: Vo=adj; DSC1: Vi=2.5-5.5V
U12-U14 = U-ETA5050: Part Name: LDO; Part Number: C070111104620; Manufacture: ETA; DSC1: Vi=2.5-5.5V; DSC2: Vo=adj; DSC3: Io=500mA; DSC5: Iq=40uA; ID: 28; Solder: 推荐

## Sheet P17.SchDoc
size 420 x 297 mm
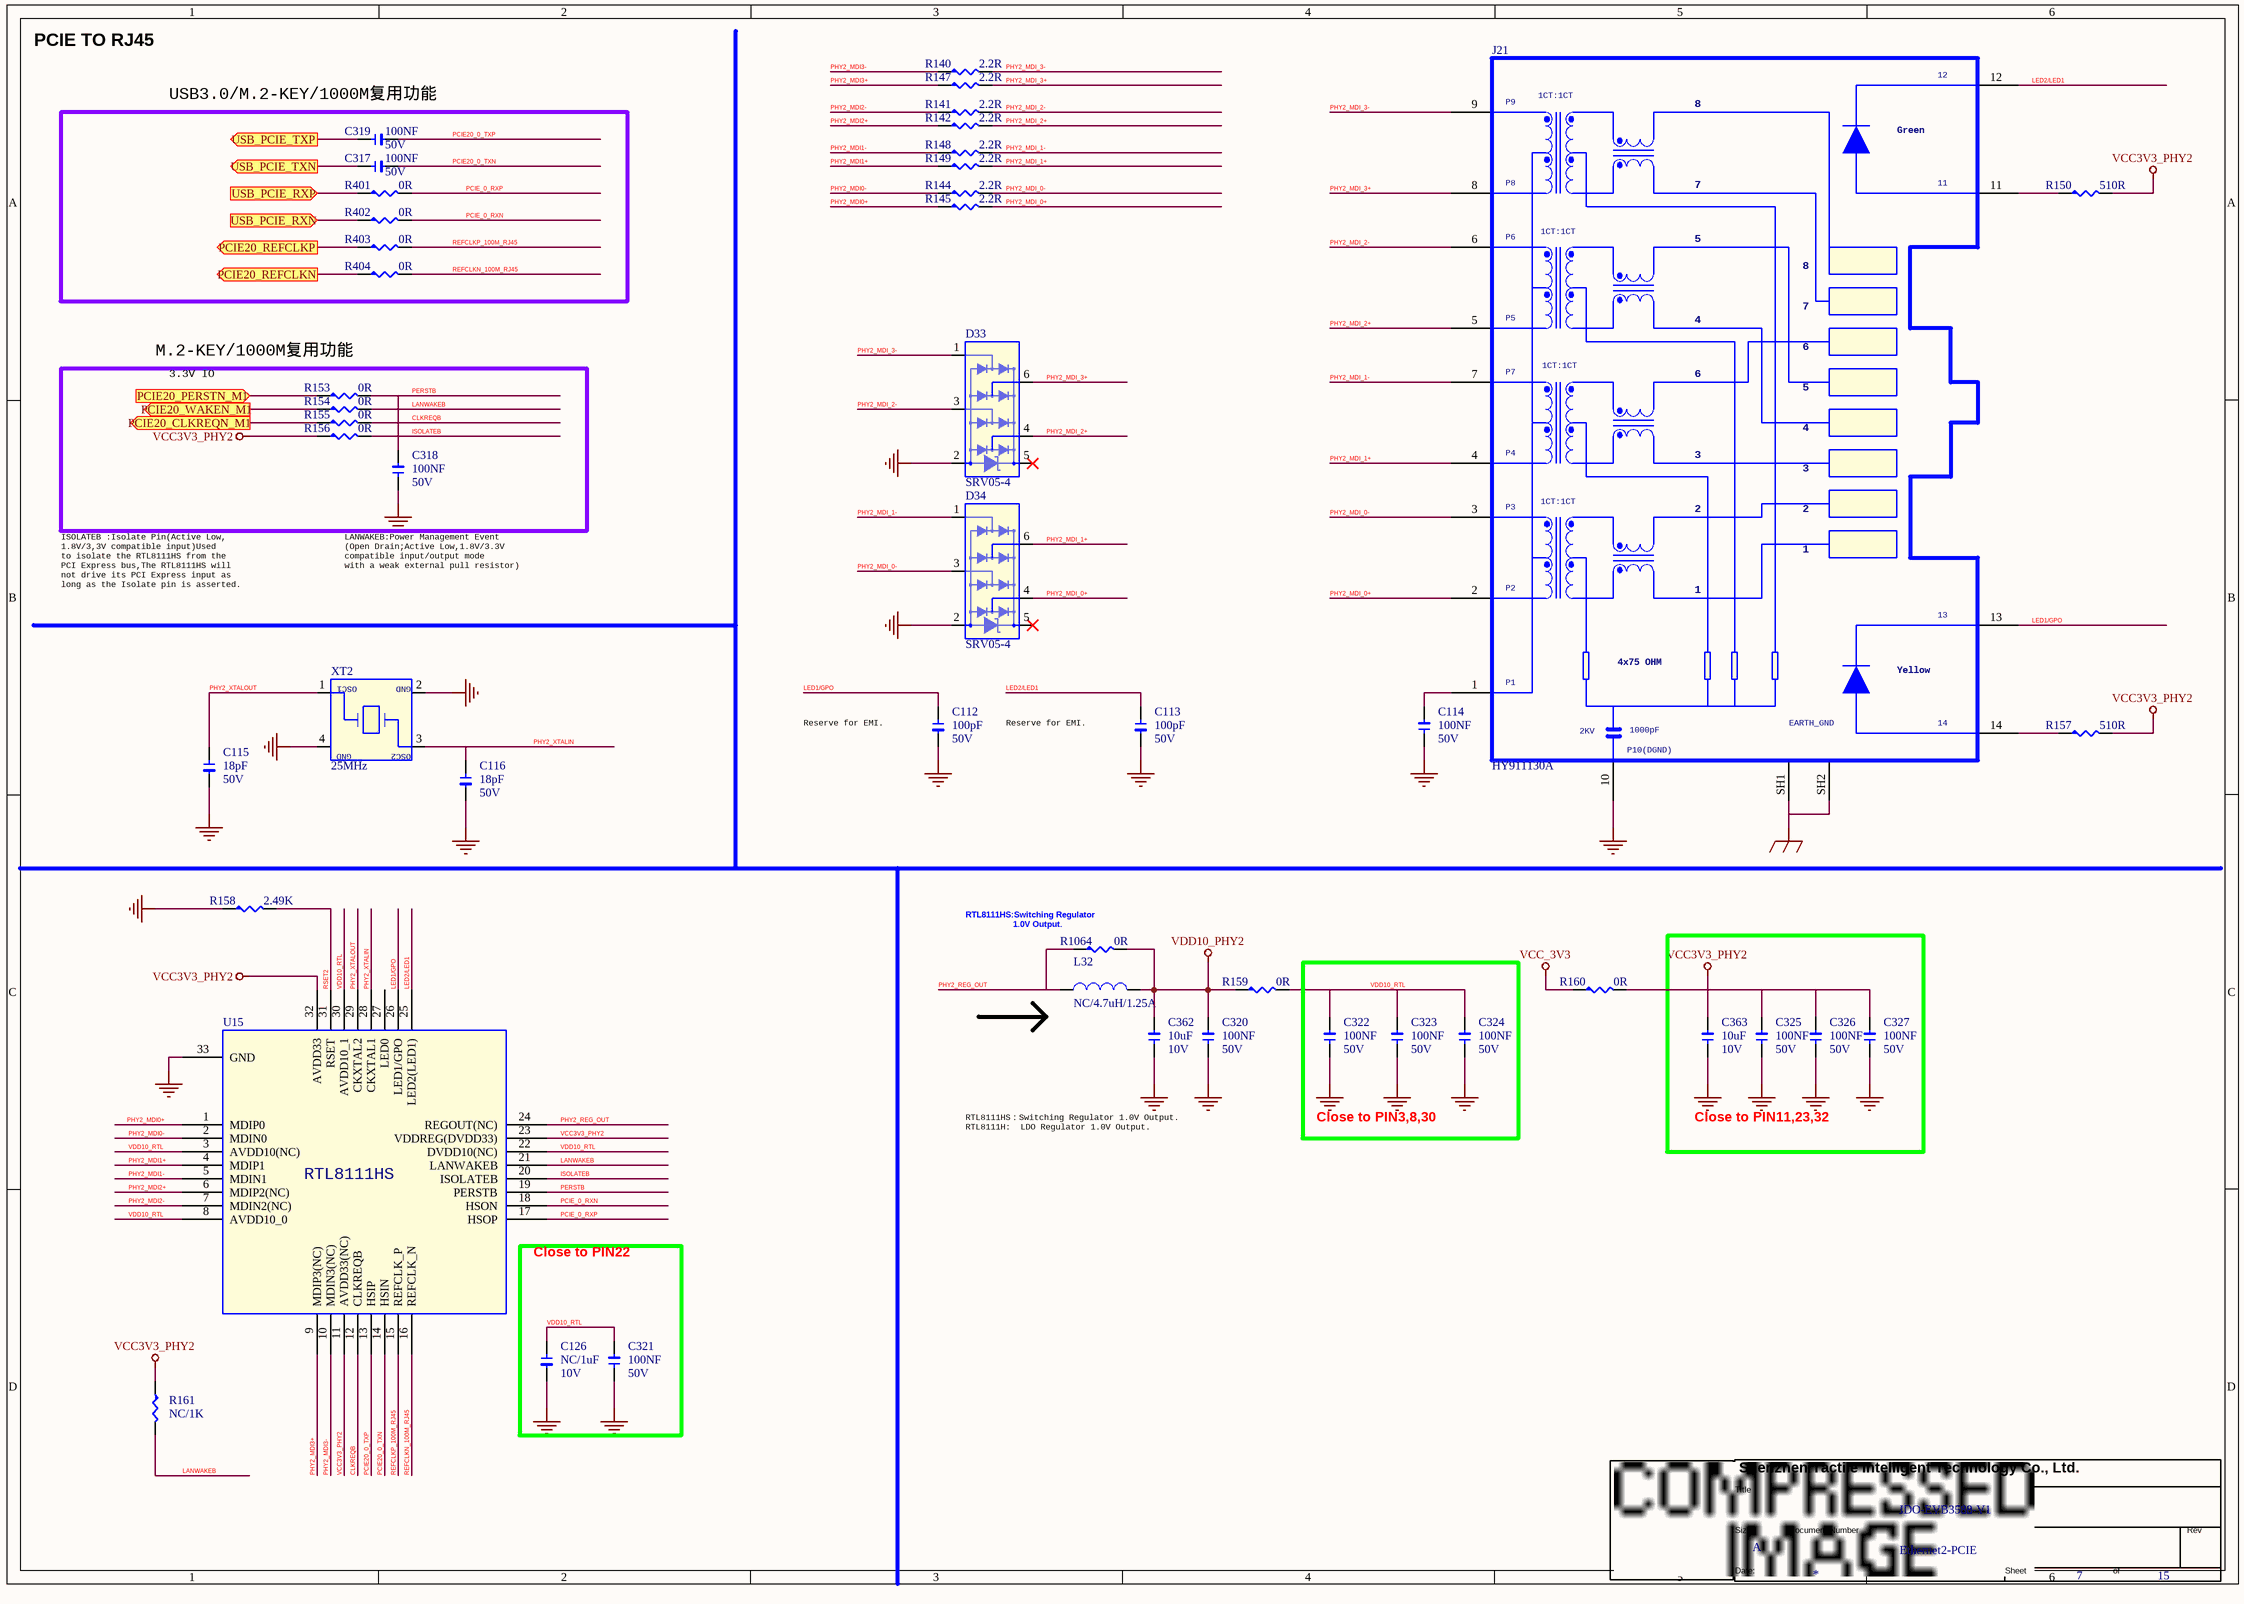
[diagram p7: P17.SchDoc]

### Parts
(Parts that share a designator on the sheet are numbered #1, #2 ... from top to bottom, then left to right.)
*#5  Page Count: 15  Page Number: 7  Page Size: A  Title: IDO-EVB3588-V1  Doc: Ethernet2-PCIE  (hidden comment: TitleBlock1)  (graphical)
C112  100pF  DSC2: 50V  [1206]
C113  100pF  DSC2: 50V  [1206]
C114  100NF  DSC2: 50V  [1206]
C115  18pF  DSC2: 50V  [1206]
C116  18pF  DSC2: 50V  [1206]
C126  NC/1uF  DSC2: 10V  [1206]
C317  100NF  DSC2: 50V  [1206]
C318  100NF  DSC2: 50V  [1206]
C319  100NF  DSC2: 50V  [1206]
C320  100NF  DSC2: 50V  [1206]
C321  100NF  DSC2: 50V  [1206]
C322  100NF  DSC2: 50V  [1206]
C323  100NF  DSC2: 50V  [1206]
C324  100NF  DSC2: 50V  [1206]
C325  100NF  DSC2: 50V  [1206]
C326  100NF  DSC2: 50V  [1206]
C327  100NF  DSC2: 50V  [1206]
C362  10uF  DSC2: 10V  [1206]
C363  10uF  DSC2: 10V  [1206]
D33  SRV05-4  [SOT23-6]
D34  SRV05-4  [SOT23-6]
J21  HY911130A  [RJ45-TH_HY911130A]
L32  NC/4.7uH/1.25A  [IND_252012]
R140  2.2R  [R0402]
R141  2.2R  [R0402]
R142  2.2R  [R0402]
R144  2.2R  [R0402]
R145  2.2R  [R0402]
R147  2.2R  [R0402]
R148  2.2R  [R0402]
R149  2.2R  [R0402]
R150  510R  [R0402]
R153  0R  [R0402]
R154  0R  [R0402]
R155  0R  [R0402]
R156  0R  [R0402]
R157  510R  [R0402]
R158  2.49K  [R0402]
R159  0R  [R0402]
R160  0R  [R0402]
R161  NC/1K  [R0402]
R401  0R  [R0402]
R402  0R  [R0402]
R403  0R  [R0402]
R404  0R  [R0402]
R1064  0R  [R0805]
U15  RTL8111HS  [QFN-32_4x4x04P]  (value not drawn)
XT2  25MHz  [xtal_32x25_4p]

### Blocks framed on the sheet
USB3.0/M.2-KEY/1000M复用功能: C317 C319 R401-R404
M.2-KEY/1000M复用功能: C318 R153-R156
Close to PIN3,8,30: C322-C324
Close to PIN11,23,32: C325-C327 C363
Close to PIN22: C126 C321

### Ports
PCIE20_CLKREQN_M1 (out), PCIE20_PERSTN_M1 (in), PCIE20_REFCLKN (out), PCIE20_REFCLKP (out), PCIE20_WAKEN_M1 (out), USB_PCIE_RXN (in), USB_PCIE_RXP (in), USB_PCIE_TXN (out), USB_PCIE_TXP (out)

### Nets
GND: C112.2 C113.2 C114.1 C115.2 C116.2 C126.2 C318.1 C320.1 C321.1 C322.1 C323.1 C324.1 C325.1 C326.1 C327.1 C362.1 C363.1 D33.2 D34.2 J21.10(GND) R158.1 U15.33(GND) XT2.2 XT2.4
GND_EARTH: J21.SH1 J21.SH2
VCC3V3_PHY2: C325.2 C326.2 C327.2 C363.2 R150.2 R156.1 R157.2 R160.2 R161.1 U15.11(AVDD33(NC)) U15.23(VDDREG(DVDD33)) U15.32(AVDD33)
VCC_3V3: R160.1
VDD10_PHY2: C320.2 C362.2 L32.2 R159.1 R1064.2
CLKREQB: R155.2 U15.12(CLKREQB)
ISOLATEB: R156.2 U15.20(ISOLATEB)
LANWAKEB: R154.2 R161.2 U15.21(LANWAKEB)
LED1/GPO: C112.1 J21.13(Y_LED-) U15.26(LED1/GPO)
LED2/LED1: C113.1 J21.12(G_LED-) U15.25(LED2(LED1))
PCIE20_0_TXN: C317.2 U15.14(HSIN)
PCIE20_0_TXP: C319.2 U15.13(HSIP)
PCIE_0_RXN: R402.2 U15.18(HSON)
PCIE_0_RXP: R401.2 U15.17(HSOP)
PERSTB: C318.2 R153.2 U15.19(PERSTB)
PHY2_MDI0+: R145.1 U15.1(MDIP0)
PHY2_MDI0-: R144.1 U15.2(MDIN0)
PHY2_MDI1+: R149.1 U15.4(MDIP1)
PHY2_MDI1-: R148.1 U15.5(MDIN1)
PHY2_MDI2+: R142.1 U15.6(MDIP2(NC))
PHY2_MDI2-: R141.1 U15.7(MDIN2(NC))
PHY2_MDI3+: R147.1 U15.9(MDIP3(NC))
PHY2_MDI3-: R140.1 U15.10(MDIN3(NC))
PHY2_MDI_0+: D34.4 J21.2(MDI_0+) R145.2
PHY2_MDI_0-: D34.3 J21.3(MDI_0-) R144.2
PHY2_MDI_1+: D34.6 J21.4(MDI_1+) R149.2
PHY2_MDI_1-: D34.1 J21.7(MDI_1-) R148.2
PHY2_MDI_2+: D33.4 J21.5(MDI_2+) R142.2
PHY2_MDI_2-: D33.3 J21.6(MDI_2-) R141.2
PHY2_MDI_3+: D33.6 J21.8(MDI_3+) R147.2
PHY2_MDI_3-: D33.1 J21.9(MDI_3-) R140.2
PHY2_REG_OUT: L32.1 R1064.1 U15.24(REGOUT(NC))
PHY2_XTALIN: C116.1 U15.28(CKXTAL1) XT2.3
PHY2_XTALOUT: C115.1 U15.29(CKXTAL2) XT2.1
REFCLKN_100M_RJ45: R404.2 U15.16(REFCLK_N)
REFCLKP_100M_RJ45: R403.2 U15.15(REFCLK_P)
RSET2: R158.2 U15.31(RSET)
VDD10_RTL: C126.1 C321.2 C322.2 C323.2 C324.2 R159.2 U15.3(AVDD10(NC)) U15.8(AVDD10_0) U15.22(DVDD10(NC)) U15.30(AVDD10_1)
NetC114_2: C114.2 J21.1(CT1/2/3/4)
NetC317_1: C317.1 ; port USB_PCIE_TXN
NetC319_1: C319.1 ; port USB_PCIE_TXP
NetJ21_11: J21.11(G_LED+) R150.1
NetJ21_14: J21.14(Y_LED+) R157.1
NetM1_28: R403.1 ; port PCIE20_REFCLKP
NetM1_29: R404.1 ; port PCIE20_REFCLKN
NetM1_72: R155.1 ; port PCIE20_CLKREQN_M1
NetM1_73: R154.1 ; port PCIE20_WAKEN_M1
NetM1_74: R153.1 ; port PCIE20_PERSTN_M1
NetR401_1: R401.1 ; port USB_PCIE_RXP
NetR402_1: R402.1 ; port USB_PCIE_RXN

Not connected (* = marked no-connect by the designer): D33 5*; D34 5*; U15 27(LED0)

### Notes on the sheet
- PCIE TO RJ45
- 3.3V IO
- ISOLATEB :Isolate Pin(Active Low,
  1.8V/3,3V compatible input)Used
  to isolate the RTL8111HS from the
  PCI Express bus,The RTL8111HS will
  not drive its PCI Express input as
  long as the Isolate pin is asserted.
- LANWAKEB:Power Management Event
  (Open Drain;Active Low,1.8V/3.3V
  compatible input/output mode
  with a weak external pull resistor)
- Reserve for EMI.
- (near R1064) RTL8111HS:Switching Regulator
  1.0V Output.
- RTL8111HS：Switching Regulator 1.0V Output.
  RTL8111H:  LDO Regulator 1.0V Output.

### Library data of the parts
C112 C113 = C-0402: Manufacture: 三星¦国巨¦村田; Part Name: 贴片电容; Part Number: C020102120040; ID: 40; DSC3: C0G; DSC1: ±5%; ERP Number: 1010200152; PCB Footprint: C0402
C114 = C-0402: Part Number: C020102120061; Part Name: 贴片电容; Manufacture: 三星¦国巨¦村田; PCB Footprint: C0402; ERP Number: 1010200128; DSC1: ±10%; DSC3: X7R; ID: 61
C115 C116 = C-0402_Dup2: Manufacture: 三星¦国巨¦村田; Part Name: 贴片电容; Part Number: C020102120027; ID: 27; DSC3: C0G; DSC1: ±5%; ERP Number: 1010200091; PCB Footprint: C0402
C126 = C-0402: Manufacture: 三星¦国巨¦村田; Part Name: 贴片电容; Part Number: C020102120064; PCB Footprint: C0402; ID: 64; DSC3: X5R; DSC1: ±10%; ERP Number: 1010200054
C317-C319 = C-0402_Dup2: as C1014 on sheet P16
C320 C322-C327 = C-0402: Manufacture: 三星¦国巨¦村田; Part Name: 贴片电容; Part Number: C020102120061; ID: 61; DSC3: X7R; DSC1: ±10%; ERP Number: 1010200128; PCB Footprint: C0402
C321 = C-0402: Part Number: C020102120061; Part Name: 贴片电容; Manufacture: 三星¦国巨¦村田; ERP Number: 1010200128; DSC1: ±10%; DSC3: X7R; ID: 61; PCB Footprint: C0402
C362 C363 = C-0603: as C1015 on sheet P16
D33 D34 = DI-TVS-SRV05-4: Part Number: C040602260015; Part Name: TVS; Manufacture: 伯恩半导体; ERP Number: 1010800050; DSC1: 单向; DSC2: Vrwm=5V; DSC3: VBR=6V; DSC4: Vc=13V; DSC5: Ipp=3.5A; DSC6: Ppp=45W; DSC7: Cj=0.36pF; ID: 15; Solder: 量产
J21 = J-RJ45-HY911130A: Part Number: J120105074660; Part Name: RJ45; DSC1: RJ45 8P插件，内置千兆变压器(商业级)  双灯 卧式 全包无弹片, / 16x21.3x13.5mm; DSC2: 通孔弯针; DSC3: G1159A01A-GY(华强盛); DSC4: HY911130A(汉仁); ID: 15
L32 = L-IND_Dup1: Part Name: 功率电感; Manufacture: 宗成¦长江微电¦顺络; DSC1: ±20%; DSC2: Isat=1.6A; DSC3: Irms=1.25A; DSC4: 260mΩ; DSC5: 2.5*2.0*1.2mm; DSC6: WPN252012H4R7MT(顺络); DSC7: FHD252012S-4R7MT(长江微电); DSC8: ZCRH252012-4.7uH-M(宗成); ID: 54
R140-R142 R144 R145 R147-R149 = R-0402_Dup1: Part Name: 贴片电阻; Part Number: C011002080238; ERP Number: 1010200263; DSC1: ±5%; DSC2: 1/16W; ID: 238
R150 R157 = R-0402_Dup1: Part Name: 贴片电阻; Part Number: C011002080296; ERP Number: 1010200226; DSC1: ±5%; DSC2: 1/16W; ID: 296
R153-R156 = R-0402_Dup1: Part Number: C011002080217; Part Name: 贴片电阻; ID: 217; DSC2: 1/16W; DSC1: ±5%; ERP Number: 1010200100
R158 = R-0402_Dup2: Part Number: C011002080785; Part Name: 贴片电阻; ID: 785; DSC2: 1/16W; DSC1: ±1%; ERP Number: 1010200324
R159 R160 R401-R404 = R-0402_Dup1: Part Name: 贴片电阻; Part Number: C011002080217; ERP Number: 1010200100; DSC1: ±5%; DSC2: 1/16W; ID: 217
R161 = R-0402_Dup1: Part Name: 贴片电阻; Part Number: C011002080303; ERP Number: 1010200104; DSC1: ±5%; DSC2: 1/16W; ID: 303
R1064 = R-0805: Part Name: 贴片电阻; Part Number: C011002081448; ERP Number: 1010200199; DSC1: ±1%; DSC2: 1/8W; ID: 1,448
U15 = RL5877_0
XT2 = XTAL-4P_Dup1: Part Name: 贴片无源晶振; Part Number: C050102290006; Manufacture: 泰晶; CLASS: IC; DSC1: 40Ω; DSC2: ±10ppm; DSC3: 12pF; DSC4: -40℃~+85℃; DSC5: 3.2*2.5mm 4P; ID: 6

## Sheet P18.SchDoc
size 594 x 420 mm
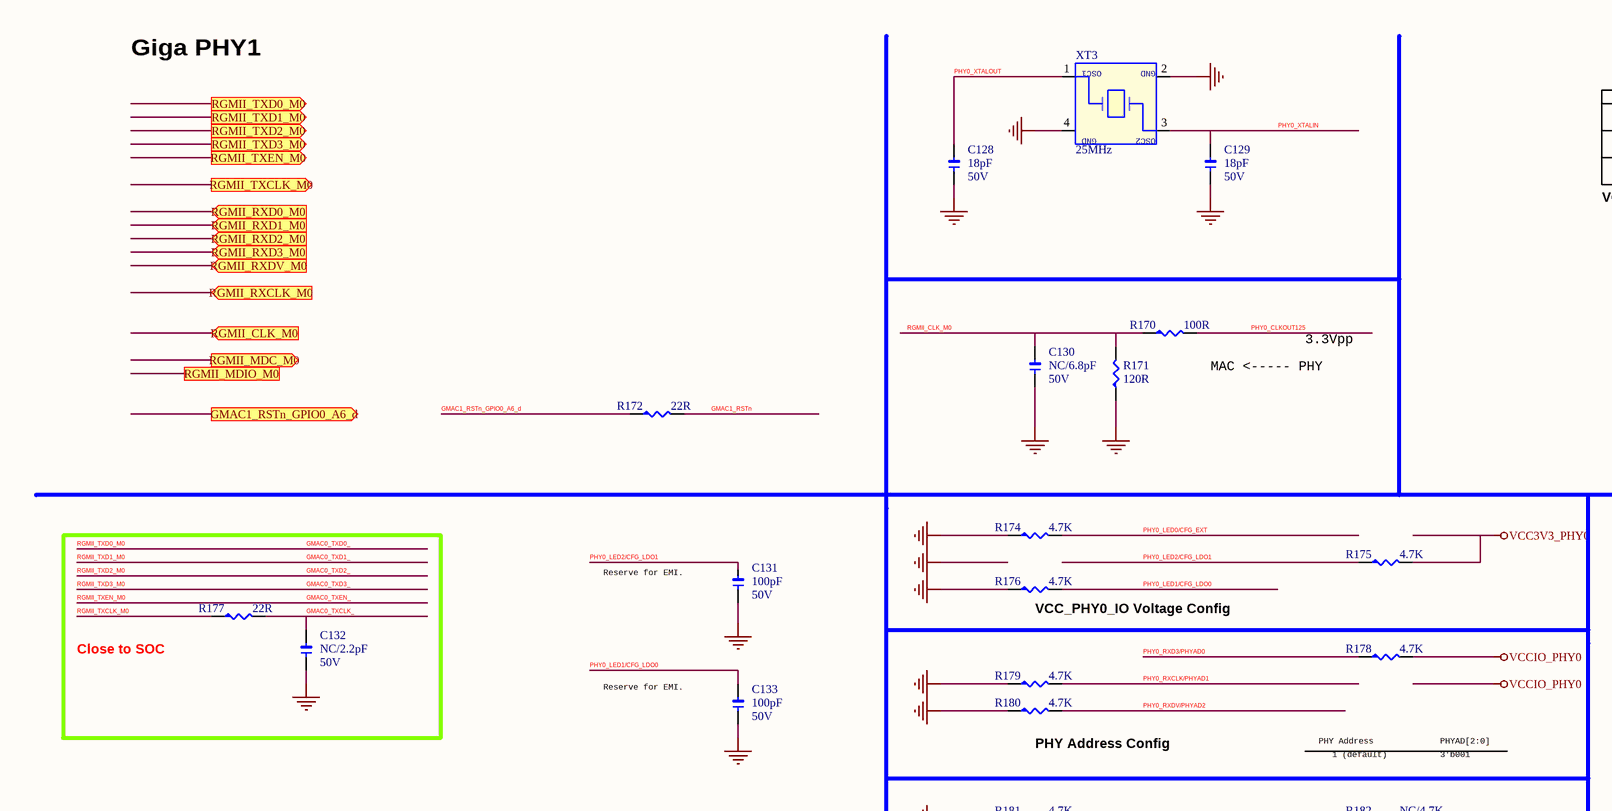
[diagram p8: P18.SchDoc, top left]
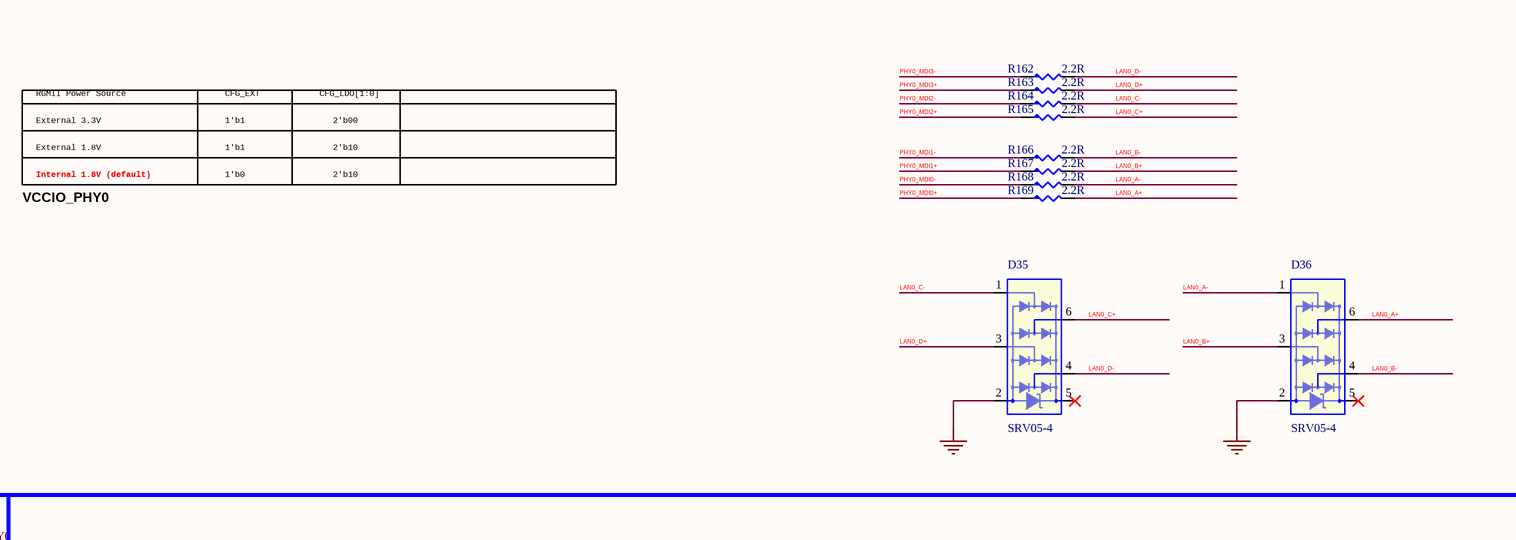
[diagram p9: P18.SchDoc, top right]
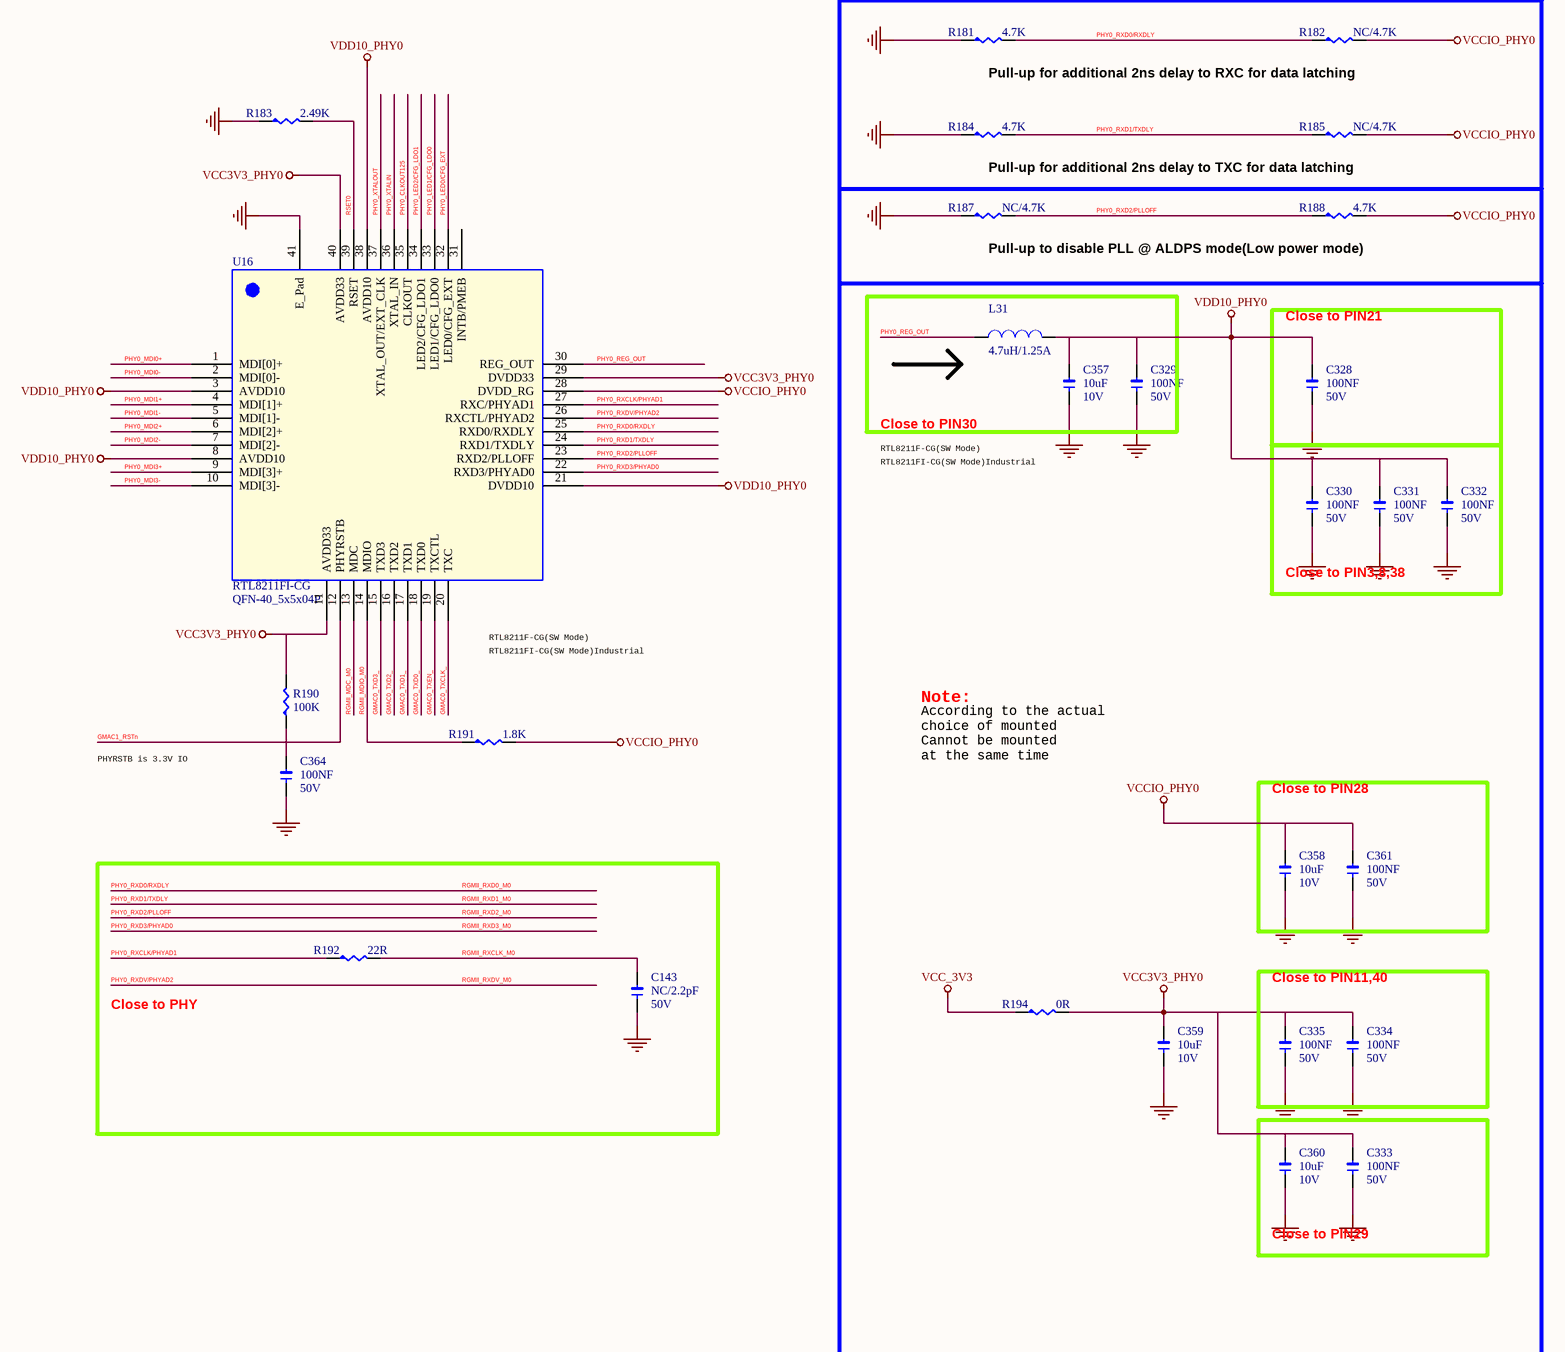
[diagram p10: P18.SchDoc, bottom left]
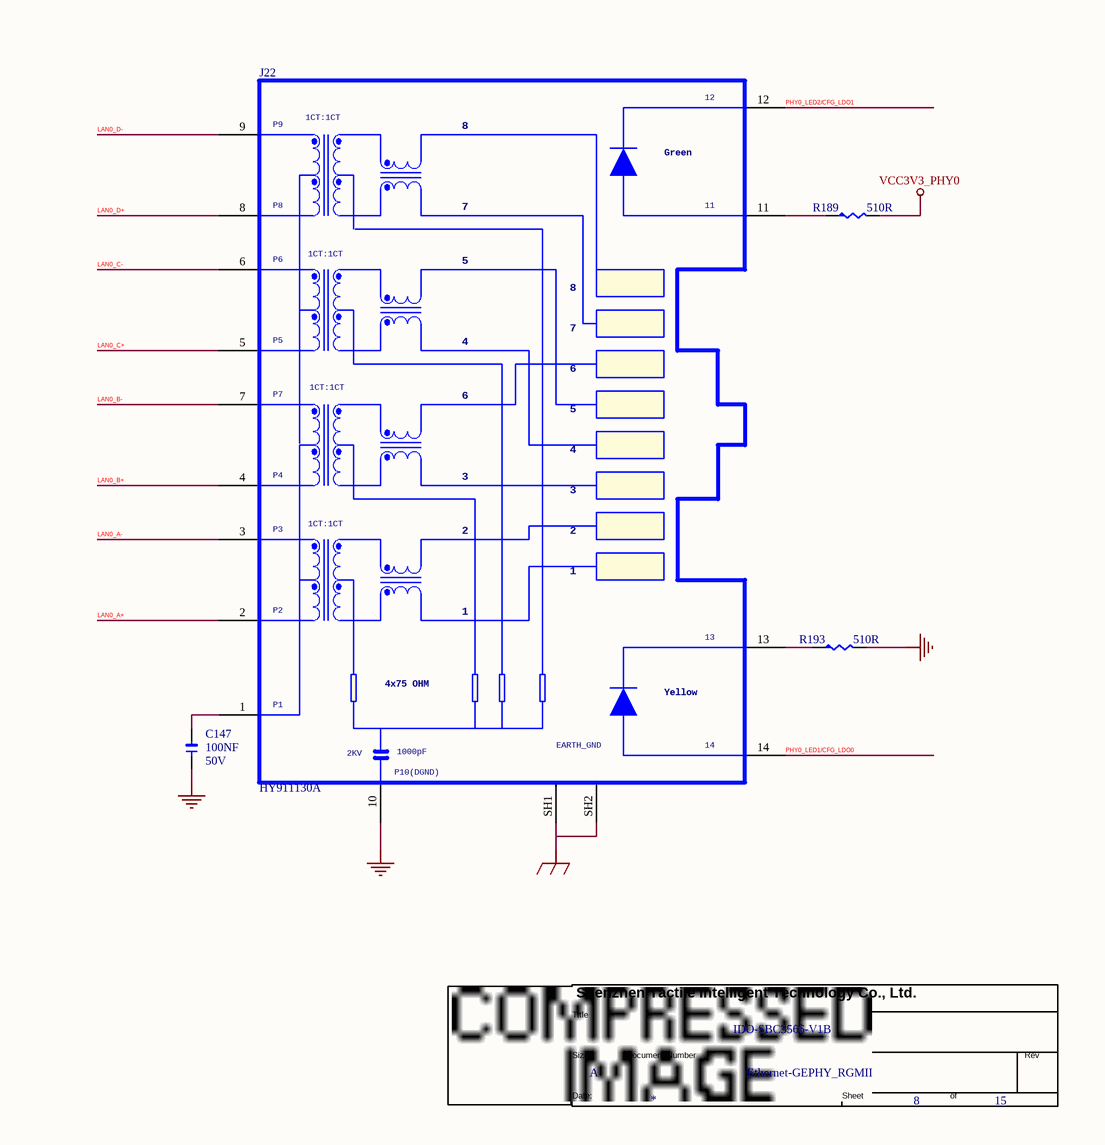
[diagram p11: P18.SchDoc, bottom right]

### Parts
(Parts that share a designator on the sheet are numbered #1, #2 ... from top to bottom, then left to right.)
*#6  Page Count: 15  Page Number: 8  Page Size: A  Title: IDO-SBC3566-V1B  Doc: Ethernet-GEPHY_RGMII  (hidden comment: TitleBlock1)  (graphical)
C128  18pF  DSC2: 50V  [1206]
C129  18pF  DSC2: 50V  [1206]
C130  NC/6.8pF  DSC2: 50V  [1206]
C131  100pF  DSC2: 50V  [1206]
C132  NC/2.2pF  DSC2: 50V  [1206]
C133  100pF  DSC2: 50V  [1206]
C143  NC/2.2pF  DSC2: 50V  [1206]
C147  100NF  DSC2: 50V  [1206]
C328  100NF  DSC2: 50V  [1206]
C329  100NF  DSC2: 50V  [1206]
C330  100NF  DSC2: 50V  [1206]
C331  100NF  DSC2: 50V  [1206]
C332  100NF  DSC2: 50V  [1206]
C333  100NF  DSC2: 50V  [1206]
C334  100NF  DSC2: 50V  [1206]
C335  100NF  DSC2: 50V  [1206]
C357  10uF  DSC2: 10V  [1206]
C358  10uF  DSC2: 10V  [1206]
C359  10uF  DSC2: 10V  [1206]
C360  10uF  DSC2: 10V  [1206]
C361  100NF  DSC2: 50V  [1206]
C364  100NF  DSC2: 50V  [1206]
D35  SRV05-4  [SOT23-6]
D36  SRV05-4  [SOT23-6]
J22  HY911130A  [RJ45-TH_HY911130A]
L31  4.7uH/1.25A  [IND_252012]
R162  2.2R  [R0402]
R163  2.2R  [R0402]
R164  2.2R  [R0402]
R165  2.2R  [R0402]
R166  2.2R  [R0402]
R167  2.2R  [R0402]
R168  2.2R  [R0402]
R169  2.2R  [R0402]
R170  100R  [R0402]
R171  120R  [R0402]
R172  22R  [R0402]
R174  4.7K  [R0402]
R175  4.7K  [R0402]
R176  4.7K  [R0402]
R177  22R  [R0402]
R178  4.7K  [R0402]
R179  4.7K  [R0402]
R180  4.7K  [R0402]
R181  4.7K  [R0402]
R182  NC/4.7K  [R0402]
R183  2.49K  [R0402]
R184  4.7K  [R0402]
R185  NC/4.7K  [R0402]
R187  NC/4.7K  [R0402]
R188  4.7K  [R0402]
R189  510R  [R0402]
R190  100K  [R0402]
R191  1.8K  [R0402]
R192  22R  [R0402]
R193  510R  [R0402]
R194  0R  [R0402]
U16  RTL8211FI-CG  [QFN-40_5x5x04P]
XT3  25MHz  [xtal_32x25_4p]

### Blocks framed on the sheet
Close to SOC: C132 R177
Close to PIN30: C329 C357 L31
Close to PIN21: C328
Close to PIN3,8,38: C330-C332
Close to PIN28: C358 C361
Close to PHY: C143 R192
Close to PIN11,40: C334 C335
Close to PIN29: C333 C360

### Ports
GMAC1_RSTn_GPIO0_A6_d (out), RGMII_CLK_M0 (in), RGMII_MDC_M0 (out), RGMII_MDIO_M0, RGMII_RXCLK_M0 (in), RGMII_RXD0_M0 (in), RGMII_RXD1_M0 (in), RGMII_RXD2_M0 (in), RGMII_RXD3_M0 (in), RGMII_RXDV_M0 (in), RGMII_TXCLK_M0 (out), RGMII_TXD0_M0 (out), RGMII_TXD1_M0 (out), RGMII_TXD2_M0 (out), RGMII_TXD3_M0 (out), RGMII_TXEN_M0 (out)

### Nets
GND: C128.1 C129.1 C130.1 C131.1 C132.1 C133.1 C143.1 C147.1 C328.1 C329.1 C330.1 C331.1 C332.1 C333.1 C334.1 C335.1 C357.1 C358.1 C359.1 C360.1 C361.1 C364.1 D35.2 D36.2 J22.10(GND) R171.1 R174.1 R176.1 R179.1 R180.1 R181.1 R183.1 R184.1 R187.1 R193.2 U16.41(E_Pad) XT3.2 XT3.4
GND_EARTH: J22.SH1 J22.SH2
VCC3V3_PHY0: C333.2 C334.2 C335.2 C359.2 C360.2 R175.2 R189.2 R190.2 R194.2 U16.11(AVDD33) U16.29(DVDD33) U16.40(AVDD33)
VCC_3V3: R194.1
VCCIO_PHY0: C358.2 C361.2 R178.2 R182.2 R185.2 R188.2 R191.2 U16.28(DVDD_RG)
VDD10_PHY0: C328.2 C329.2 C330.2 C331.2 C332.2 C357.2 L31.2 U16.3(AVDD10) U16.8(AVDD10) U16.21(DVDD10) U16.38(AVDD10)
GMAC0_TXCLK_: C132.2 R177.2 U16.20(TXC)
GMAC0_TXD0_: U16.18(TXD0)  [also labelled RGMII_TXD0_M0]
GMAC0_TXD1_: U16.17(TXD1)  [also labelled RGMII_TXD1_M0]
GMAC0_TXD2_: U16.16(TXD2)  [also labelled RGMII_TXD2_M0]
GMAC0_TXD3_: U16.15(TXD3)  [also labelled RGMII_TXD3_M0]
GMAC0_TXEN_: U16.19(TXCTL)  [also labelled RGMII_TXEN_M0]
GMAC1_RSTn: C364.2 R172.2 R190.1 U16.12(PHYRSTB)
GMAC1_RSTn_GPIO0_A6_d: R172.1
LAN0_A+: D36.6 J22.2(MDI_0+) R169.2
LAN0_A-: D36.1 J22.3(MDI_0-) R168.2
LAN0_B+: D36.3 J22.4(MDI_1+) R167.2
LAN0_B-: D36.4 J22.7(MDI_1-) R166.2
LAN0_C+: D35.6 J22.5(MDI_2+) R165.2
LAN0_C-: D35.1 J22.6(MDI_2-) R164.2
LAN0_D+: D35.3 J22.8(MDI_3+) R163.2
LAN0_D-: D35.4 J22.9(MDI_3-) R162.2
PHY0_CLKOUT125: R170.2 U16.35(CLKOUT)
PHY0_LED0/CFG_EXT: R174.2 U16.32(LED0/CFG_EXT)
PHY0_LED1/CFG_LDO0: C133.2 J22.14(Y_LED+) R176.2 U16.33(LED1/CFG_LDO0)
PHY0_LED2/CFG_LDO1: C131.2 J22.12(G_LED-) R175.1 U16.34(LED2/CFG_LDO1)
PHY0_MDI0+: R169.1 U16.1(MDI[0]+)
PHY0_MDI0-: R168.1 U16.2(MDI[0]-)
PHY0_MDI1+: R167.1 U16.4(MDI[1]+)
PHY0_MDI1-: R166.1 U16.5(MDI[1]-)
PHY0_MDI2+: R165.1 U16.6(MDI[2]+)
PHY0_MDI2-: R164.1 U16.7(MDI[2]-)
PHY0_MDI3+: R163.1 U16.9(MDI[3]+)
PHY0_MDI3-: R162.1 U16.10(MDI[3]-)
PHY0_REG_OUT: L31.1 U16.30(REG_OUT)
PHY0_RXCLK/PHYAD1: R179.2 R192.1 U16.27(RXC/PHYAD1)
PHY0_RXD0/RXDLY: R181.2 R182.1 U16.25(RXD0/RXDLY)  [also labelled RGMII_RXD0_M0]
PHY0_RXD1/TXDLY: R184.2 R185.1 U16.24(RXD1/TXDLY)  [also labelled RGMII_RXD1_M0]
PHY0_RXD2/PLLOFF: R187.2 R188.1 U16.23(RXD2/PLLOFF)  [also labelled RGMII_RXD2_M0]
PHY0_RXD3/PHYAD0: R178.1 U16.22(RXD3/PHYAD0)  [also labelled RGMII_RXD3_M0]
PHY0_RXDV/PHYAD2: R180.2 U16.26(RXCTL/PHYAD2)  [also labelled RGMII_RXDV_M0]
PHY0_XTALIN: C129.2 U16.36(XTAL_IN) XT3.3
PHY0_XTALOUT: C128.2 U16.37(XTAL_OUT/EXT_CLK) XT3.1
RGMII_CLK_M0: C130.2 R170.1 R171.2
RGMII_MDC_M0: U16.13(MDC)
RGMII_MDIO_M0: R191.1 U16.14(MDIO)
RGMII_RXCLK_M0: C143.2 R192.2
RGMII_TXCLK_M0: R177.1
RSET0: R183.2 U16.39(RSET)
NetC147_2: C147.2 J22.1(CT1/2/3/4)
NetJ22_11: J22.11(G_LED+) R189.1
NetJ22_13: J22.13(Y_LED-) R193.1

Not connected (* = marked no-connect by the designer): D35 5*; D36 5*; U16 31(INTB/PMEB)

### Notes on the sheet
- Giga PHY1
- RGMII Power Source
- CFG_EXT
- CFG_LDO[1:0]
- External 3.3V
- External 1.8V
- 1'b1
- 2'b00
- 2'b10
- VCCIO_PHY0
- Internal 1.8V (default)
- 1'b0
- (near R170) MAC <----- PHY
- 3.3Vpp
- Reserve for EMI.
- (near R176) VCC_PHY0_IO Voltage Config
- (near R180) PHY Address Config
- PHY Address
- 1 (default)
- PHYAD[2:0]
- 3'b001
- Pull-up for additional 2ns delay to RXC for data latching
- Pull-up for additional 2ns delay to TXC for data latching
- Pull-up to disable PLL @ ALDPS mode(Low power mode)
- RTL8211F-CG(SW Mode)
- RTL8211FI-CG(SW Mode)Industrial
- Note:
- According to the actual
  choice of mounted
  Cannot be mounted
  at the same time
- PHYRSTB is 3.3V IO

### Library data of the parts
C128 C129 = C-0402_Dup1: Part Number: C020102120027; Part Name: 贴片电容; Manufacture: 三星¦国巨¦村田; ERP Number: 1010200091; DSC1: ±5%; DSC3: C0G; ID: 27; PCB Footprint: C0402
C130 = C-0402_Dup1: Manufacture: 三星¦国巨¦村田; Part Name: 贴片电容; Part Number: C020102120018; PCB Footprint: C0402; ID: 18; DSC3: C0G; DSC1: ±0.25PF; ERP Number: 1010200056
C131 = C-0402_Dup1: Manufacture: 三星¦国巨¦村田; Part Name: 贴片电容; Part Number: C020102120040; ID: 40; DSC3: C0G; DSC1: ±5%; ERP Number: 1010200152; PCB Footprint: C0402
C132 C143 = C-0402_Dup1: Manufacture: 三星¦国巨¦村田; Part Name: 贴片电容; Part Number: C020102120013; PCB Footprint: C0402; ID: 13; DSC3: C0G; DSC1: ±0.1PF; ERP Number: 1010200109
C133 = C-0402_Dup1: Part Number: C020102120040; Part Name: 贴片电容; Manufacture: 三星¦国巨¦村田; ERP Number: 1010200152; DSC1: ±5%; DSC3: C0G; ID: 40; PCB Footprint: C0402
C147 = C-0402: as C320 on sheet P17
C328-C335 C361 C364 = C-0402: as C321 on sheet P17
C357-C360 = C-0603: as C1013 on sheet P16
D35 = DI-ESD-SRV05-4: Part Number: C040602260015; Part Name: TVS; Manufacture: 伯恩半导体; ERP Number: 1010800050; DSC1: 单向; DSC2: Vrwm=5V; DSC3: VBR=6V; DSC4: Vc=13V; DSC5: Ipp=3.5A; DSC6: Ppp=45W; DSC7: Cj=0.36pF; ID: 15; Solder: 量产
D36 = DI-ESD-SRV05-4: Manufacture: 伯恩半导体; Part Name: TVS; Part Number: C040602260015; Solder: 量产; ID: 15; DSC7: Cj=0.36pF; DSC6: Ppp=45W; DSC5: Ipp=3.5A; DSC4: Vc=13V; DSC3: VBR=6V; DSC2: Vrwm=5V; DSC1: 单向; ERP Number: 1010800050
J22 = J-RJ45-HY911130A: Part Name: RJ45; Part Number: J120105074660; ID: 15; DSC4: HY911130A(汉仁); DSC3: G1159A01A-GY(华强盛); DSC2: 通孔弯针; DSC1: RJ45 8P插件，内置千兆变压器(商业级)  双灯 卧式 全包无弹片, / 16x21.3x13.5mm
L31 = L-IND_Dup1: as L32 on sheet P17
R162-R169 = R-0402_Dup3: Part Name: 贴片电阻; Part Number: C011002080238; ERP Number: 1010200263; DSC1: ±5%; DSC2: 1/16W; ID: 238
R170 = R-0402_Dup3: Part Number: C011002080279; Part Name: 贴片电阻; ID: 279; DSC2: 1/16W; DSC1: ±5%; ERP Number: 1010200160
R171 = R-0402_Dup3: Part Name: 贴片电阻; Part Number: C011002080281; DSC1: ±5%; DSC2: 1/16W; ID: 281
R172 = R-0402_Dup3: as R124 on sheet P16
R174-R176 R178-R181 R184 R188 = R-0402_Dup3: Part Name: 贴片电阻; Part Number: C011002080320; ERP Number: 1010200177; DSC1: ±5%; DSC2: 1/16W; ID: 320
R177 R192 = R-0402_Dup3: as R75 on sheet P15
R182 R185 R187 = R-0402_Dup3: Part Number: C011002080320; Part Name: 贴片电阻; ID: 320; DSC2: 1/16W; DSC1: ±5%; ERP Number: 1010200177
R183 = R-0402_Dup3: Part Number: C011002080785; Part Name: 贴片电阻; ID: 785; DSC2: 1/16W; DSC1: ±1%; ERP Number: 1010200324
R189 = R-0402_Dup1: Part Number: C011002080296; Part Name: 贴片电阻; ID: 296; DSC2: 1/16W; DSC1: ±5%; ERP Number: 1010200226
R190 = R-0402_Dup3: as R80 on sheet P15
R191 = R-0402_Dup3: Part Number: C011002080309; Part Name: 贴片电阻; ID: 309; DSC2: 1/16W; DSC1: ±5%
R193 = R-0402_Dup1: as R150 on sheet P17
R194 = R-0402_Dup3: as R1172 on sheet P16
U16 = U-RTL8211F-CG: Manufacture: REALTEK(瑞昱); Part Name: 以太网芯片; Part Number: C100105104678; ID: 59; DSC3: -40℃~+85℃; DSC2: QFN40，5mm×5mm，0.4mm Pitch; DSC1: Ethernet Transceivers RGMII, RMII 10/100/1000 Base-T PHY
XT3 = XTAL-4P_Dup1: Manufacture: 泰晶; Part Number: C050102290006; Part Name: 贴片无源晶振; CLASS: IC; ID: 6; DSC5: 3.2*2.5mm 4P; DSC4: -40℃~+85℃; DSC3: 12pF; DSC2: ±10ppm; DSC1: 40Ω

## Sheet P19.SchDoc
size 420 x 297 mm
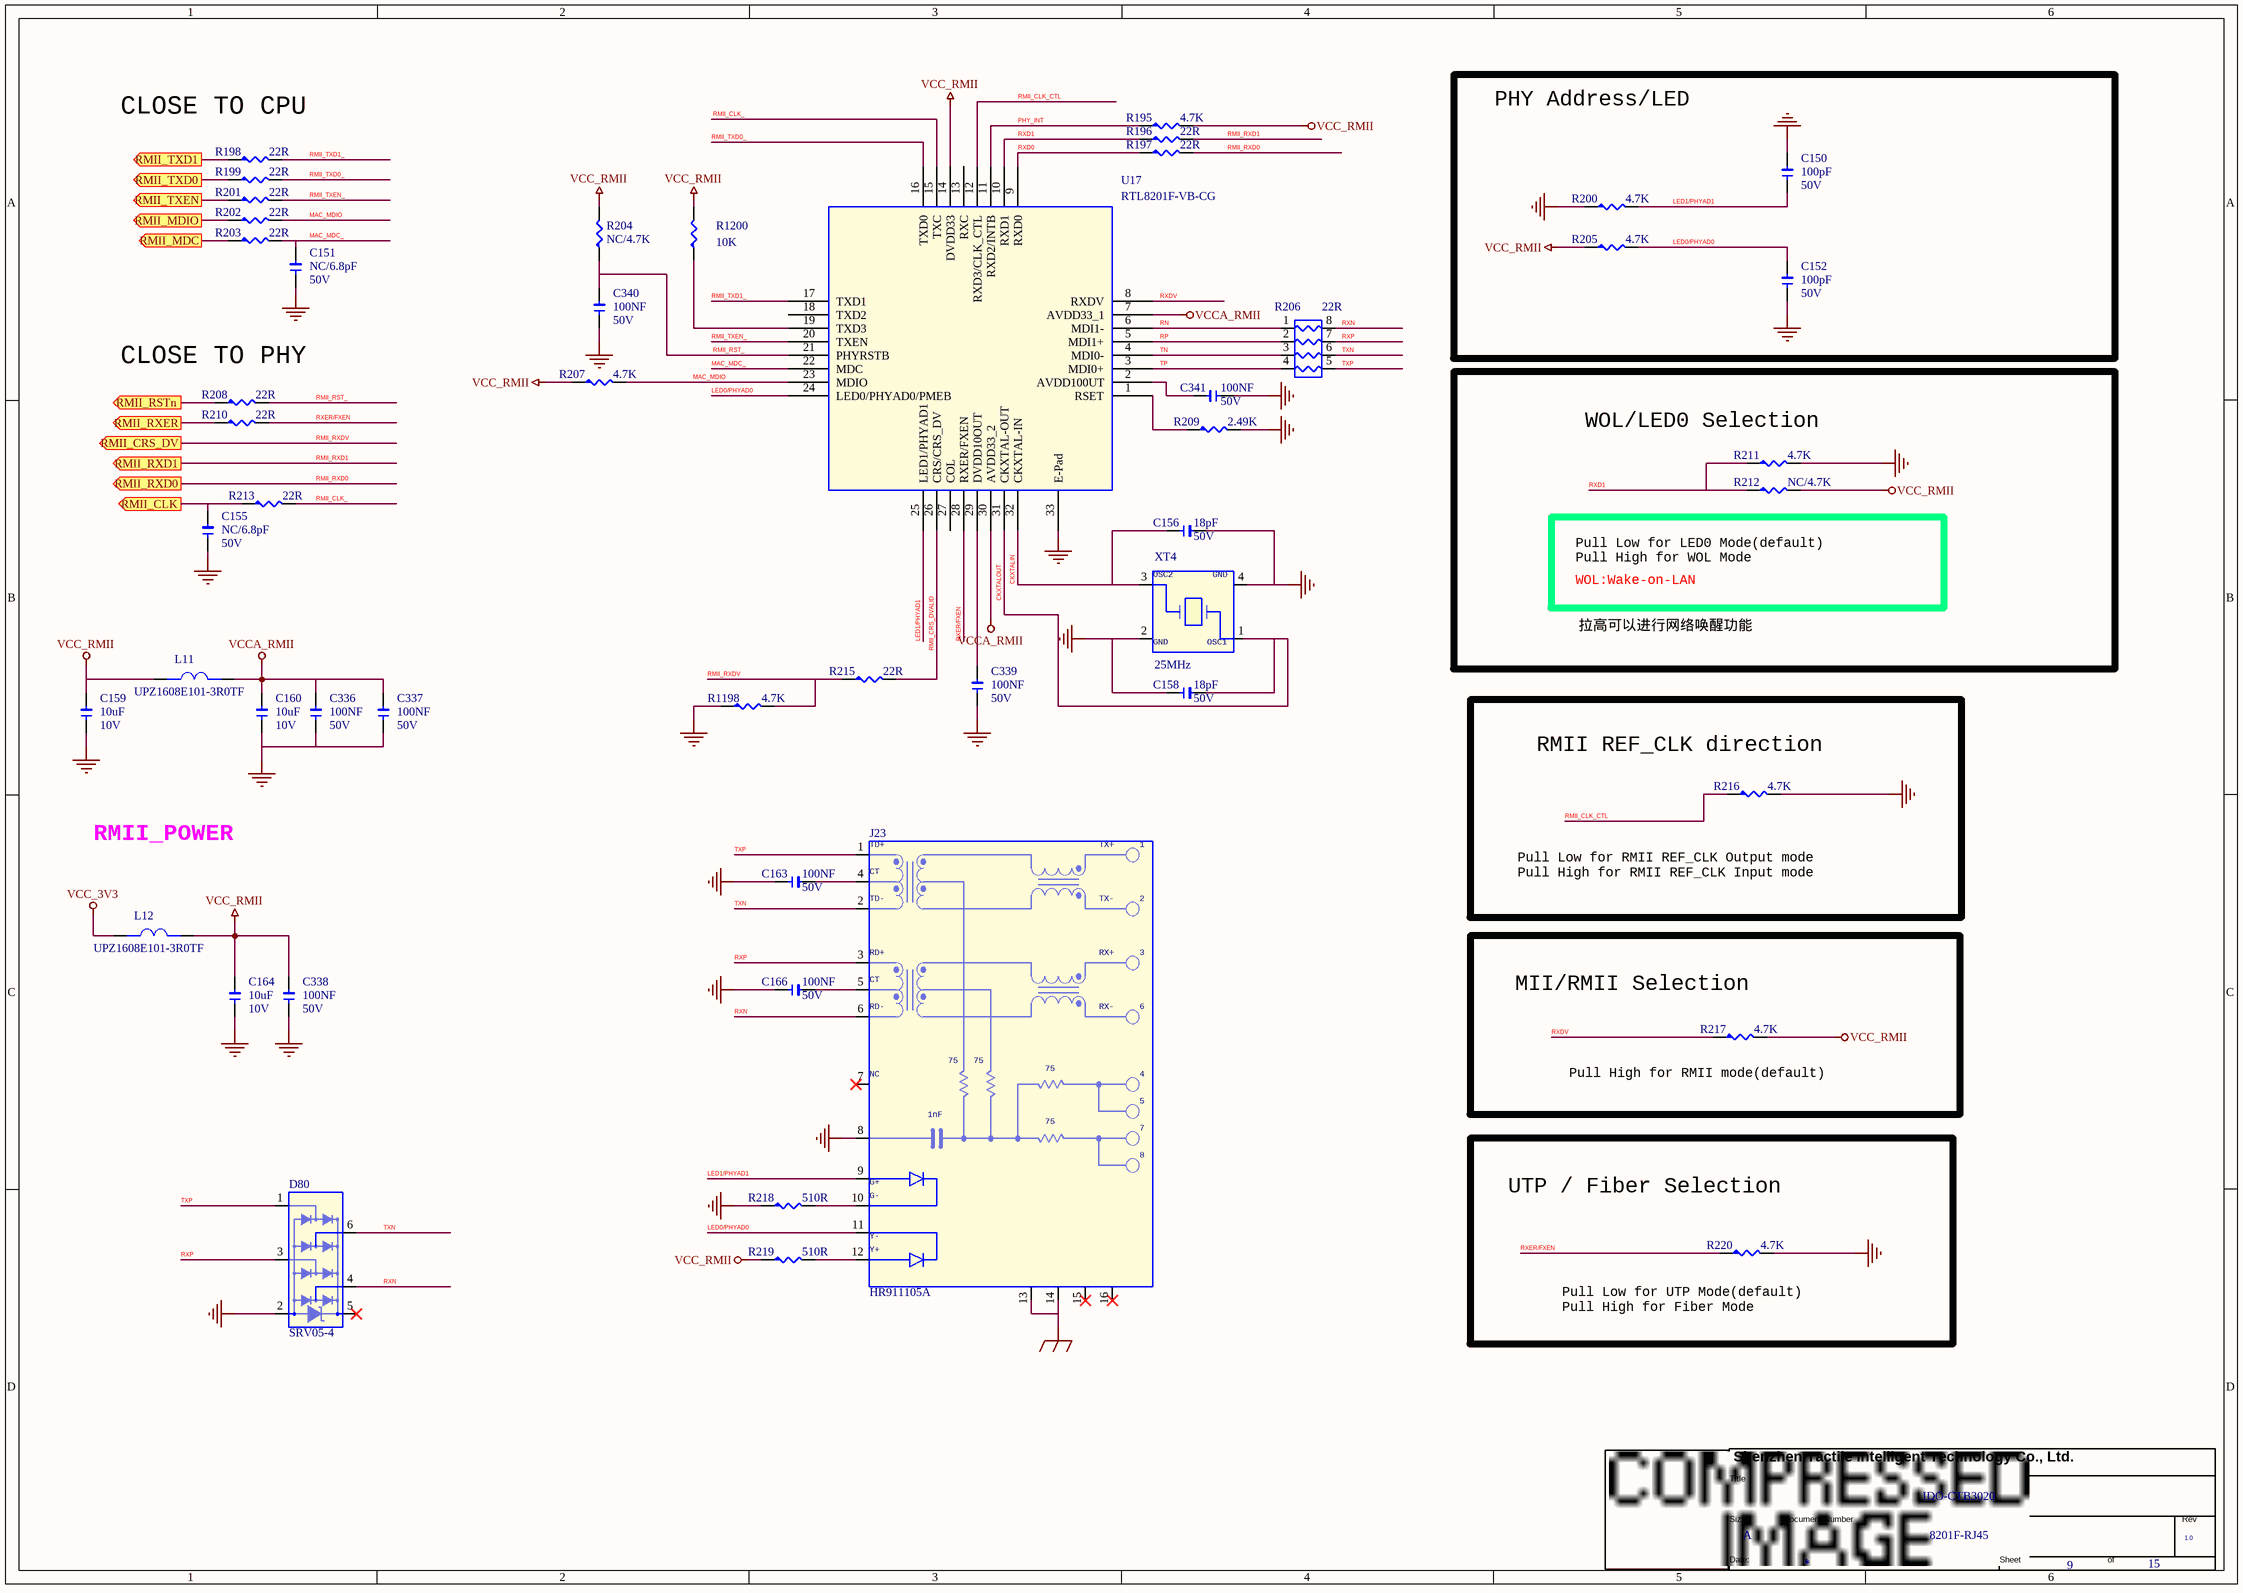
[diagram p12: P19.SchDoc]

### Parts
(Parts that share a designator on the sheet are numbered #1, #2 ... from top to bottom, then left to right.)
*#7  Page Count: 15  Page Number: 9  Page Size: A  Title: IDO-CTB3020  RevCode: 1.0  Doc: 8201F-RJ45  (hidden comment: TitleBlock1)  (graphical)
C150  100pF  DSC2: 50V  [1206]
C151  NC/6.8pF  DSC2: 50V  [1206]
C152  100pF  DSC2: 50V  [1206]
C155  NC/6.8pF  DSC2: 50V  [1206]
C156  18pF  DSC2: 50V  [1206]
C158  18pF  DSC2: 50V  [1206]
C159  10uF  DSC2: 10V  [1206]
C160  10uF  DSC2: 10V  [1206]
C163  100NF  DSC2: 50V  [1206]
C164  10uF  DSC2: 10V  [1206]
C166  100NF  DSC2: 50V  [1206]
C336  100NF  DSC2: 50V  [1206]
C337  100NF  DSC2: 50V  [1206]
C338  100NF  DSC2: 50V  [1206]
C339  100NF  DSC2: 50V  [1206]
C340  100NF  DSC2: 50V  [1206]
C341  100NF  DSC2: 50V  [1206]
D80  SRV05-4  [SOT23-6]
J23  HR911105A  [RJ45-TH_HR911105A]
L11  UPZ1608E101-3R0TF  [L0603]
L12  UPZ1608E101-3R0TF  [L0603]
R195  4.7K  [R0402]
R196  22R  [R0402]
R197  22R  [R0402]
R198  22R  [R0402]
R199  22R  [R0402]
R200  4.7K  [R0402]
R201  22R  [R0402]
R202  22R  [R0402]
R203  22R  [R0402]
R204  NC/4.7K  [R0402]
R205  4.7K  [R0402]
R206  22R  [RN_0402X4]
R207  4.7K  [R0402]
R208  22R  [R0402]
R209  2.49K  [R0402]
R210  22R  [R0402]
R211  4.7K  [R0402]
R212  NC/4.7K  [R0402]
R213  22R  [R0402]
R215  22R  [R0402]
R216  4.7K  [R0402]
R217  4.7K  [R0402]
R218  510R  [R0402]
R219  510R  [R0402]
R220  4.7K  [R0402]
R1198  4.7K  [R0402]
R1200  10K  [R0402]
U17  RTL8201F-VB-CG  [QFN32-5X5]
XT4  25MHz  [xtal_32x25_4p]

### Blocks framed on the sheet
PHY Address/LED: C150 C152 R200 R205
WOL/LED0 Selection: R211 R212
RMII REF_CLK direction: R216
MII/RMII Selection: R217
UTP / Fiber Selection: R220

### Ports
RMII_CLK (out), RMII_CRS_DV (out), RMII_MDC (out), RMII_MDIO (out), RMII_RSTn (out), RMII_RXD0 (out), RMII_RXD1 (out), RMII_RXER (out), RMII_TXD0 (out), RMII_TXD1 (out), RMII_TXEN (out)

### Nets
GND: C150.2 C151.1 C152.1 C155.1 C156.2 C158.1 C159.1 C160.1 C163.1 C164.1 C166.1 C336.1 C337.1 C338.1 C339.1 C340.1 C341.1 D80.2 J23.8(P8) R200.1 R209.2 R211.2 R216.2 R218.1 R220.2 R1198.1 U17.33(E-Pad) XT4.2 XT4.4
GND_EARTH: J23.13(P13) J23.14(P14)
VCC_3V3: L12.1
VCC_RMII: C159.2 C164.2 C338.2 L11.1 L12.2 R195.2 R204.2 R205.1 R207.1 R212.2 R217.2 R219.1 R1200.2 U17.14(DVDD33)
VCCA_RMII: C160.2 C336.2 C337.2 L11.2 U17.7(AVDD33_1) U17.30(AVDD33_2)
CKXTALIN: C156.1 U17.32(CKXTAL-IN) XT4.3
CKXTALOUT: C158.2 U17.31(CKXTAL-OUT) XT4.1
LED0/PHYAD0: C152.2 J23.11(Y-) R205.2 U17.24(LED0/PHYAD0/PMEB)
LED1/PHYAD1: C150.1 J23.9(G+) R200.2 U17.25(LED1/PHYAD1)
MAC_MDC_: C151.2 R203.2 U17.22(MDC)
MAC_MDIO: R202.2 R207.2 U17.23(MDIO)
PHY_INT: R195.1 U17.11(RXD2/INTB)
RMII_CLK_: R213.2 U17.15(TXC)
RMII_CLK_CTL: R216.1 U17.12(RXD3/CLK_CTL)
RMII_CRS_DVALID: R215.2 U17.26(CRS/CRS_DV)
RMII_RST_: C340.2 R204.1 R208.2 U17.21(PHYRSTB)
RMII_RXD0: R197.2 ; port RMII_RXD0
RMII_RXD1: R196.2 ; port RMII_RXD1
RMII_RXDV: R215.1 R1198.2 ; port RMII_CRS_DV
RMII_TXD0_: R199.2 U17.16(TXD0)
RMII_TXD1_: R198.2 U17.17(TXD1)
RMII_TXEN_: R201.2 U17.20(TXEN)
RN: R206.1 U17.6(MDI1-)
RP: R206.2 U17.5(MDI1+)
RXD0: R197.1 U17.9(RXD0)
RXD1: R196.1 R211.1 R212.1 U17.10(RXD1)
RXDV: R217.1 U17.8(RXDV)
RXER/FXEN: R210.2 R220.1 U17.28(RXER/FXEN)
RXN: D80.4 J23.6(P6) R206.8
RXP: D80.3 J23.3(P3) R206.7
TN: R206.3 U17.4(MDI0-)
TP: R206.4 U17.3(MDI0+)
TXN: D80.6 J23.2(P2) R206.6
TXP: D80.1 J23.1(P1) R206.5
NetC155_2: C155.2 R213.1 ; port RMII_CLK
NetC163_2: C163.2 J23.4(P4)
NetC166_2: C166.2 J23.5(P5)
NetC339_2: C339.2 U17.29(DVDD10OUT)
NetC341_2: C341.2 U17.2(AVDD100UT)
NetJ23_10: J23.10(G-) R218.2
NetJ23_12: J23.12(Y+) R219.2
NetM1_32: R208.1 ; port RMII_RSTn
NetM1_33: R210.1 ; port RMII_RXER
NetM1_38: R201.1 ; port RMII_TXEN
NetM1_39: R198.1 ; port RMII_TXD1
NetM1_40: R199.1 ; port RMII_TXD0
NetM1_41: R202.1 ; port RMII_MDIO
NetM1_42: R203.1 ; port RMII_MDC
NetR209_1: R209.1 U17.1(RSET)
NetR1200_1: R1200.1 U17.19(TXD3)

Not connected (* = marked no-connect by the designer): D80 5*; J23 7(P7)* 15* 16*; U17 13(RXC) 18(TXD2) 27(COL)

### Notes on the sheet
- CLOSE TO CPU
- CLOSE TO PHY
- (near R212) Pull Low for LED0 Mode(default)
  Pull High for WOL Mode
- WOL:Wake-on-LAN
- 拉高可以进行网络唤醒功能
- RMII_POWER
- Pull Low for RMII REF_CLK Output mode
  Pull High for RMII REF_CLK Input mode
- (near R217) Pull High for RMII mode(default)
- (near R220) Pull Low for UTP Mode(default)
  Pull High for Fiber Mode

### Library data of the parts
C150 C152 = C-0402_Dup1: as C131 on sheet P18
C151 = C-0402_Dup1: as C130 on sheet P18
C155 = C-0402_Dup1: as C95 on sheet P16
C156 C158 = C-0402_Dup1: Part Number: C020102120027; Part Name: 贴片电容; Manufacture: 三星¦国巨¦村田; PCB Footprint: C0402; ERP Number: 1010200091; DSC1: ±5%; DSC3: C0G; ID: 27
C159 C160 = C-0603: as C1013 on sheet P16
C163 C166 C336 C340 C341 = C-0402: as C114 on sheet P17
C164 = C-0603: as C96 on sheet P16
C337-C339 = C-0402: Manufacture: 三星¦国巨¦村田; Part Name: 贴片电容; Part Number: C020102120061; PCB Footprint: C0402; ID: 61; DSC3: X7R; DSC1: ±10%; ERP Number: 1010200128
D80 = DI-TVS-SRV05-4: Manufacture: 伯恩半导体; Part Name: TVS; Part Number: C040602260015; Solder: 量产; ID: 15; DSC7: Cj=0.36pF; DSC6: Ppp=45W; DSC5: Ipp=3.5A; DSC4: Vc=13V; DSC3: VBR=6V; DSC2: Vrwm=5V; DSC1: 单向; ERP Number: 1010800050
J23 = J-RJ45-HR911105A_0: Part Number: J120103060004; REF: J00-0061; DESIG: 10/100 base TX LXT971A; BOI: RJ45; FAB: PULSE; DEV: CON_PULSE_J00-61; ID: 4; DSC4: HR911105A(汉仁); DSC3: H1159A01A-GY(华强盛); DSC2: 通孔弯针; DSC1: RJ45 8P插件 内置百兆变压器(商业级)  双灯 卧式 全包无弹片, / 16x21.3x13.5mm
L11 = FB-0603_Dup1: SMD Multilayer Ferrite Chip Bead,3A,30Ohm,0.03R; Manufacturer: SUNLORD; Manufacture2 P/N: PBY160808T-400Y-N; Manufacture P/N: PZ1608D300-3R0TF; Part Number: C060502370005; Manufacture: 顺络; Part Name: 贴片磁珠; PN Type: SMD FERRITE BEAD; ID: 5; DSC4: 电源线; DSC3: DCR=30mΩ; DSC1: 100Ω@100MHz; ERP Number: 1010200207
L12 = FB-0603_Dup1: SMD Multilayer Ferrite Chip Bead,3A,30Ohm,0.03R; Manufacturer: SUNLORD; Manufacture2 P/N: PBY160808T-400Y-N; Manufacture P/N: PZ1608D300-3R0TF; Part Number: C060502370005; Part Name: 贴片磁珠; Manufacture: 顺络; PN Type: SMD FERRITE BEAD; ERP Number: 1010200207; DSC1: 100Ω@100MHz; DSC3: DCR=30mΩ; DSC4: 电源线; ID: 5
R195 R200 R204 R205 R211 R216 R217 R220 R1198 = R-0402_Dup3: as R174-R176 on sheet P18
R196 R198 R199 R201 R203 R208 R210 R215 = R-0402_Dup3: as R75 on sheet P15
R197 R202 R213 = R-0402_Dup3: as R124 on sheet P16
R206 = RN_0402X4: Part Name: 贴片排阻; Part Number: C010302090004; ID: 4; DSC1: ±5%; DSC2: 1/16W
R207 R212 = R-0402_Dup3: as R182 on sheet P18
R209 = R-0402_Dup3: as R183 on sheet P18
R218 = R-0402_Dup3: Part Number: C011002080296; Part Name: 贴片电阻; ID: 296; DSC2: 1/16W; DSC1: ±5%; ERP Number: 1010200226
R219 = R-0402_Dup1: as R189 on sheet P18
R1200 = R-0402_Dup3: as R443 on sheet P15
U17 = U-RTL8201F-VB-CG: Manufacture: REALTEK(瑞昱); Part Name: 以太网芯片; Part Number: C100102490008; PCB Footprint: QFN-32_5x5x05P; ID: 8; DSC3: 0℃~+70℃; DSC2: QFN32，5mm×5mm，0.5mm Pitch; DSC1: Physical Layer Transceivers IEEE 802.3, 10/100 Base-T/TX/FX PHY; ERP Number: 1010100179
XT4 = XTAL-4P: Part Name: 贴片无源晶振; Part Number: C050102290006; Manufacture: 泰晶; CLASS: IC; DSC1: 40Ω; DSC2: ±10ppm; DSC3: 12pF; DSC4: -40℃~+85℃; DSC5: 3.2*2.5mm 4P

## Sheet P20.SchDoc
size 420 x 297 mm
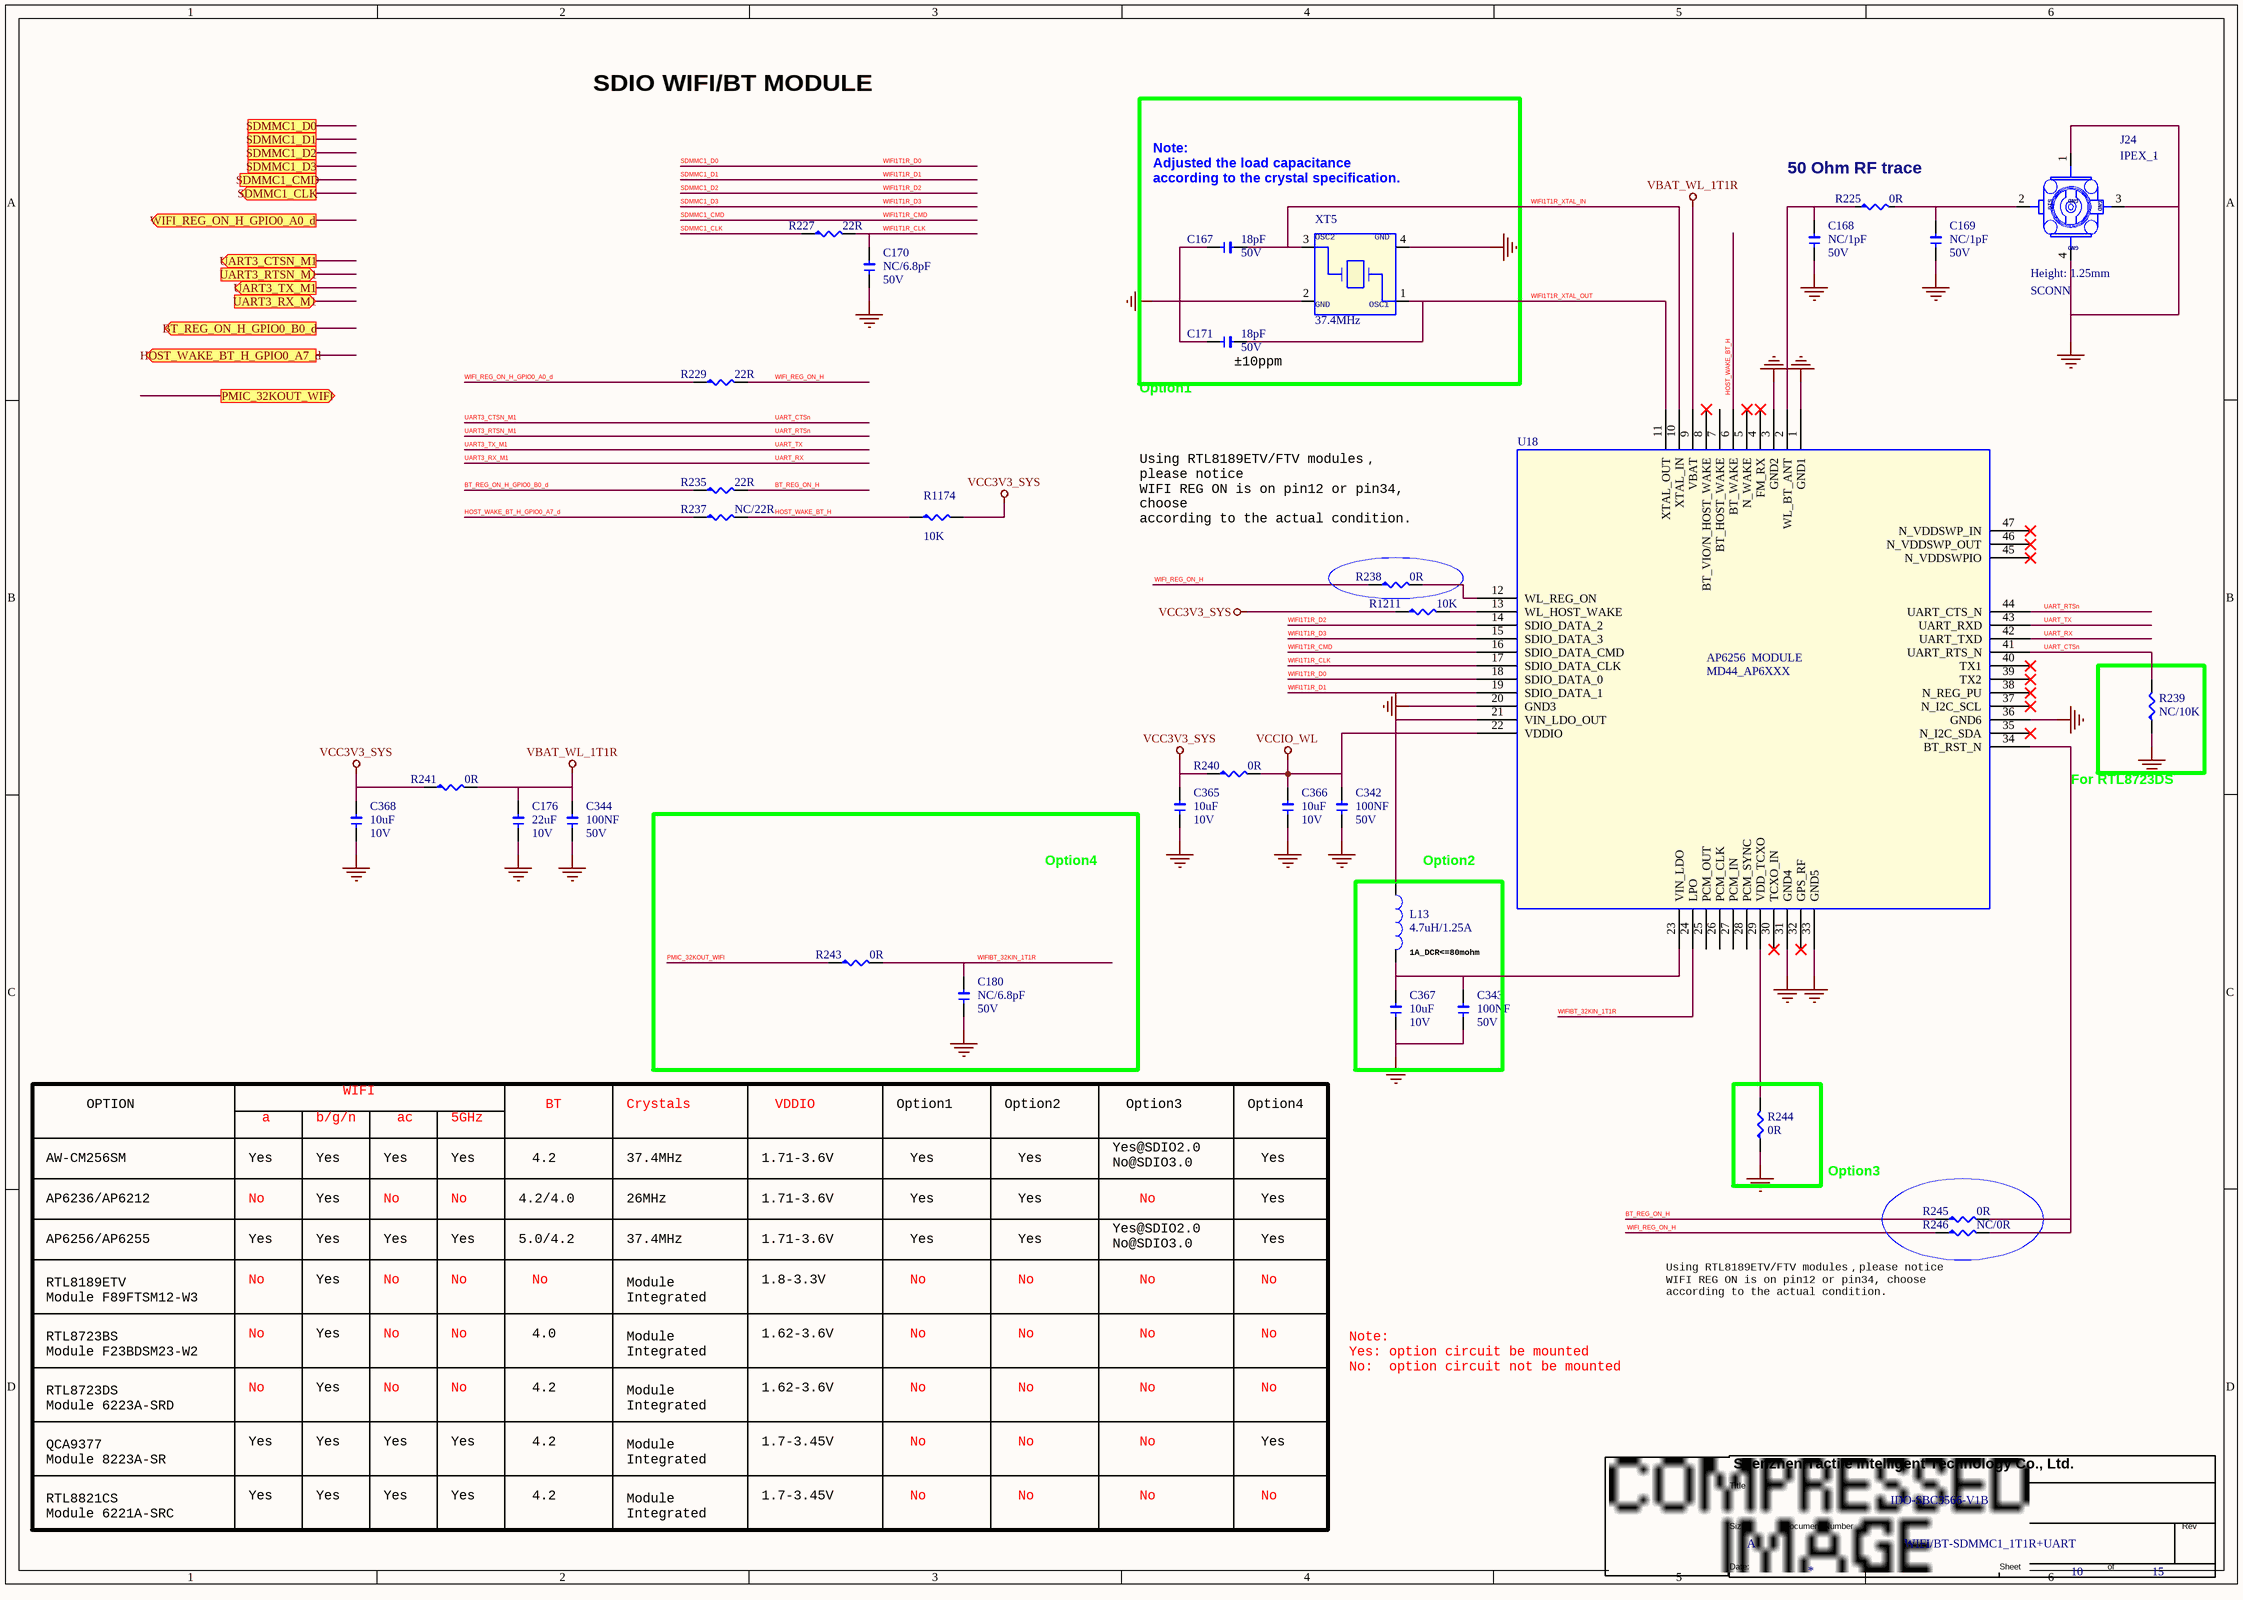
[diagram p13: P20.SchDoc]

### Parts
(Parts that share a designator on the sheet are numbered #1, #2 ... from top to bottom, then left to right.)
*#8  Page Count: 15  Page Number: 10  Page Size: A  Title: IDO-SBC3566-V1B  Doc: WIFI/BT-SDMMC1_1T1R+UART  (hidden comment: TitleBlock1)  (graphical)
C167  18pF  DSC2: 50V  [1206]
C168  NC/1pF  DSC2: 50V  [1206]
C169  NC/1pF  DSC2: 50V  [1206]
C170  NC/6.8pF  DSC2: 50V  [1206]
C171  18pF  DSC2: 50V  [1206]
C176  22uF  DSC2: 10V  [1206]
C180  NC/6.8pF  DSC2: 50V  [1206]
C342  100NF  DSC2: 50V  [1206]
C343  100NF  DSC2: 50V  [1206]
C344  100NF  DSC2: 50V  [1206]
C365  10uF  DSC2: 10V  [1206]
C366  10uF  DSC2: 10V  [1206]
C367  10uF  DSC2: 10V  [1206]
C368  10uF  DSC2: 10V  [1206]
J24  IPEX_1  Height: 1.25mm  Material: SCONN  [IPEX-001E]
L13  4.7uH/1.25A  [IND_252012]
R225  0R  [R0402]
R227  22R  [R0402]
R229  22R  [R0402]
R235  22R  [R0402]
R237  NC/22R  [R0402]
R238  0R  [R0402]
R239  NC/10K  [R0402]
R240  0R  [R0603]
R241  0R  [R0603]
R243  0R  [R0402]
R244  0R  [R0402]
R245  0R  [R0402]
R246  NC/0R  [R0402]
R1174  10K  [R0402]
R1211  10K  [R0402]
U18  AP6256  MODULE  [MD44_AP6XXX]
XT5  37.4MHz  [xtal_32x25_4p]

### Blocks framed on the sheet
±10ppm: C167 C171 XT5
Option4: C180 R243
Option2: C343 C367 L13

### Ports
BT_REG_ON_H_GPIO0_B0_d (out), HOST_WAKE_BT_H_GPIO0_A7_d (out), PMIC_32KOUT_WIFI (out), SDMMC1_CLK (out), SDMMC1_CMD, SDMMC1_D0, SDMMC1_D1, SDMMC1_D2, SDMMC1_D3, UART3_CTSN_M1 (out), UART3_RTSN_M1 (in), UART3_RX_M1 (in), UART3_TX_M1 (out), WIFI_REG_ON_H_GPIO0_A0_d (out)

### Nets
GND: C167.1 C168.1 C169.1 C170.1 C171.1 C176.1 C180.1 C342.1 C343.1 C344.1 C365.1 C366.1 C367.1 C368.1 J24.1(GND1) J24.3(GND2) J24.4(GND3) R239.1 R244.1 U18.1(GND1) U18.3(GND2) U18.20(GND3) U18.31(GND4) U18.33(GND5) U18.36(GND6) XT5.2 XT5.4
VBAT_WL_1T1R: C176.2 C344.2 R241.2 U18.9(VBAT)
VCC3V3_SYS: C365.2 C368.2 R240.1 R241.1 R1174.2 R1211.1
VCCIO_WL: C342.2 C366.2 R240.2 U18.22(VDDIO)
BT_REG_ON_H: R235.2 R245.1
BT_REG_ON_H_GPIO0_B0_d: R235.1
HOST_WAKE_BT_H: R237.2 R1174.1 U18.6(BT_WAKE)
HOST_WAKE_BT_H_GPIO0_A7_d: R237.1
PMIC_32KOUT_WIFI: R243.1
SDMMC1_CLK: R227.1
SDMMC1_CMD: U18.16(SDIO_DATA_CMD)  [also labelled WIFI1T1R_CMD]
SDMMC1_D0: U18.18(SDIO_DATA_0)  [also labelled WIFI1T1R_D0]
SDMMC1_D1: U18.19(SDIO_DATA_1)  [also labelled WIFI1T1R_D1]
SDMMC1_D2: U18.14(SDIO_DATA_2)  [also labelled WIFI1T1R_D2]
SDMMC1_D3: U18.15(SDIO_DATA_3)  [also labelled WIFI1T1R_D3]
UART3_CTSN_M1: R239.2 U18.41(UART_RTS_N)  [also labelled UART_CTSn]
UART3_RTSN_M1: U18.44(UART_CTS_N)  [also labelled UART_RTSn]
UART3_RX_M1: U18.42(UART_TXD)  [also labelled UART_RX]
UART3_TX_M1: U18.43(UART_RXD)  [also labelled UART_TX]
WIFI1T1R_CLK: C170.2 R227.2 U18.17(SDIO_DATA_CLK)
WIFI1T1R_XTAL_IN: C167.2 U18.10(XTAL_IN) XT5.3
WIFI1T1R_XTAL_OUT: C171.2 U18.11(XTAL_OUT) XT5.1
WIFI_REG_ON_H: R229.2 R238.1 R246.1
WIFI_REG_ON_H_GPIO0_A0_d: R229.1
WIFIBT_32KIN_1T1R: C180.2 R243.2 U18.24(LPO)
NetC168_2: C168.2 R225.1 U18.2(WL_BT_ANT)
NetC169_2: C169.2 J24.2(SIG) R225.2
NetC343_2: C343.2 C367.2 L13.2 U18.23(VIN_LDO)
NetL13_1: L13.1 U18.21(VIN_LDO_OUT)
NetR238_2: R238.2 U18.12(WL_REG_ON)
NetR244_2: R244.2 U18.29(VDD_TCXO)
NetR245_2: R245.2 R246.2 U18.34(BT_RST_N)
NetR1211_2: R1211.2 U18.13(WL_HOST_WAKE)

Not connected (* = marked no-connect by the designer): U18 4(FM_RX)* 5(N_WAKE)* 7(BT_HOST_WAKE) 8(BT_VIO/N_HOST_WAKE)* 25(PCM_OUT) 26(PCM_CLK) 27(PCM_IN) 28(PCM_SYNC) 30(TCXO_IN)* 32(GPS_RF)* 35(N_I2C_SDA)* 37(N_I2C_SCL)* 38(N_REG_PU)* 39(TX2)* 40(TX1)* 45(N_VDDSWPIO)* 46(N_VDDSWP_OUT)* 47(N_VDDSWP_IN)*

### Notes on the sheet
- SDIO WIFI/BT MODULE
- Note:
  Adjusted the load capacitance
  according to the crystal specification.
- (near R225) 50 Ohm RF trace
- (near C171) Option1
- (near U18) Using RTL8189ETV/FTV modules，
  please notice
  WIFI REG ON is on pin12 or pin34,
  choose
  according to the actual condition.
- For RTL8723DS
- (near L13) 1A_DCR<=80mohm
- OPTION
- a
- b/g/n
- WIFI
- ac
- 5GHz
- BT
- Crystals
- VDDIO
- Option1
- Option2
- Yes@SDIO2.0
  No@SDIO3.0
- Option3
- Option4
- AP6236/AP6212
- AW-CM256SM
- No
- Yes
- 4.2/4.0
- 4.2
- 26MHz
- 37.4MHz
- 1.71-3.6V
- AP6256/AP6255
- RTL8189ETV
  Module F89FTSM12-W3
- 5.0/4.2
- Module
  Integrated
- Using RTL8189ETV/FTV modules，please notice
  WIFI REG ON is on pin12 or pin34, choose
  according to the actual condition.
- RTL8723BS
  Module F23BDSM23-W2
- 4.0
- 1.62-3.6V
- 1.8-3.3V
- Note:
  Yes: option circuit be mounted
  No:  option circuit not be mounted
- RTL8723DS
  Module 6223A-SRD
- QCA9377
  Module 8223A-SR
- 1.7-3.45V
- RTL8821CS
  Module 6221A-SRC

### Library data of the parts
C167 C171 = C-0402_Dup1: Manufacture: 三星¦国巨¦村田; Part Name: 贴片电容; Part Number: C020102120027; ID: 27; DSC3: C0G; DSC1: ±5%; ERP Number: 1010200091; PCB Footprint: C0402
C168 C169 = C-0402_Dup1: Manufacture: 三星¦国巨¦村田; Part Name: 贴片电容; Part Number: C020102120011; ID: 11; DSC3: C0G; DSC1: ±0.1PF; PCB Footprint: C0402
C170 = C-0402_Dup1: Part Number: C020102120018; Part Name: 贴片电容; Manufacture: 三星¦国巨¦村田; ERP Number: 1010200056; DSC1: ±0.25PF; DSC3: C0G; ID: 18; PCB Footprint: C0402
C176 = C-0603: Part Number: C020107143899; Part Name: 贴片电容; Manufacture: 三星¦国巨¦村田; PCB Footprint: C0603; DSC1: ±20%; DSC3: X5R; ID: 83
C180 = C-0402_Dup1: as C130 on sheet P18
C342 C344 = C-0402: as C320 on sheet P17
C343 = C-0402: as C321 on sheet P17
C365-C367 = C-0603: as C1015 on sheet P16
C368 = C-0603: as C1013 on sheet P16
J24 = RF-PIEX-1: SMD micro Coaxial Connector Receptacle vertial; Part_Name: MHF-20279; Part Name: IPEX座; Part Number: J110103040001; ID: 1; DSC4: KH-IPEX-K501-29(金航标); DSC3: U.FL-R-SMT-1(80) 广濑; DSC2: 贴片; DSC1: 射频同轴一代IPEX板端贴片天线座子 IPEX/IPX接头 U.FL-R-SMT
L13 = L-IND_Dup1: as L32 on sheet P17
R225 R238 R244 R245 = R-0402_Dup3: as R1182-R1191 on sheet P15
R227 R235 = R-0402_Dup3: as R124 on sheet P16
R229 R237 = R-0402_Dup3: as R75 on sheet P15
R239 R1174 = R-0402_Dup3: Part Number: C011002080328; Part Name: 贴片电阻; ID: 328; DSC2: 1/16W; DSC1: ±5%; ERP Number: 1010200096
R240 = R-0603_Dup1: Part Name: 贴片电阻; Part Number: C011002081182; ERP Number: 1010200158; DSC1: ±1%; DSC2: 1/10W; ID: 1,182
R241 = R-0603_Dup1: Part Number: C011002081182; Part Name: 贴片电阻; ID: 1,182; DSC2: 1/10W; DSC1: ±1%; ERP Number: 1010200158
R243 = R-0402_Dup3: as R423 on sheet P15
R246 = R-0402_Dup3: as R1172 on sheet P16
R1211 = R-0402_Dup3: Part Name: 贴片电阻; Part Number: C011002080328; ERP Number: 1010200096; DSC1: ±5%; DSC2: 1/16W; ID: 328
U18 = MODULE_AP6XXX: WiFi+Bluetooth 4.0(HS)+FM Rx; Manufacturer PN: AP6335; Manufacturer: Ampak（正基科技）; Priority: A
XT5 = XTAL-4P_Dup1: Part Name: 贴片无源晶振; Manufacture: 爱普生; CLASS: IC; DSC1: 60Ω; DSC2: ±10ppm; DSC3: 12pF; DSC4: -40℃~+85℃; DSC5: 3.2*2.5mm 4P; ID: 13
